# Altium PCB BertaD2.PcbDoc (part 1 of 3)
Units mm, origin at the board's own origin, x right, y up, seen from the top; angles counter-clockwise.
Board outline 100.5 x 100 mm, 4 copper layers (Top Layer, Signal Layer 1, Signal Layer 2, Bottom Layer), stack 0.778 mm thick; 108 components, 216 nets, 850 pads, 807 vias.
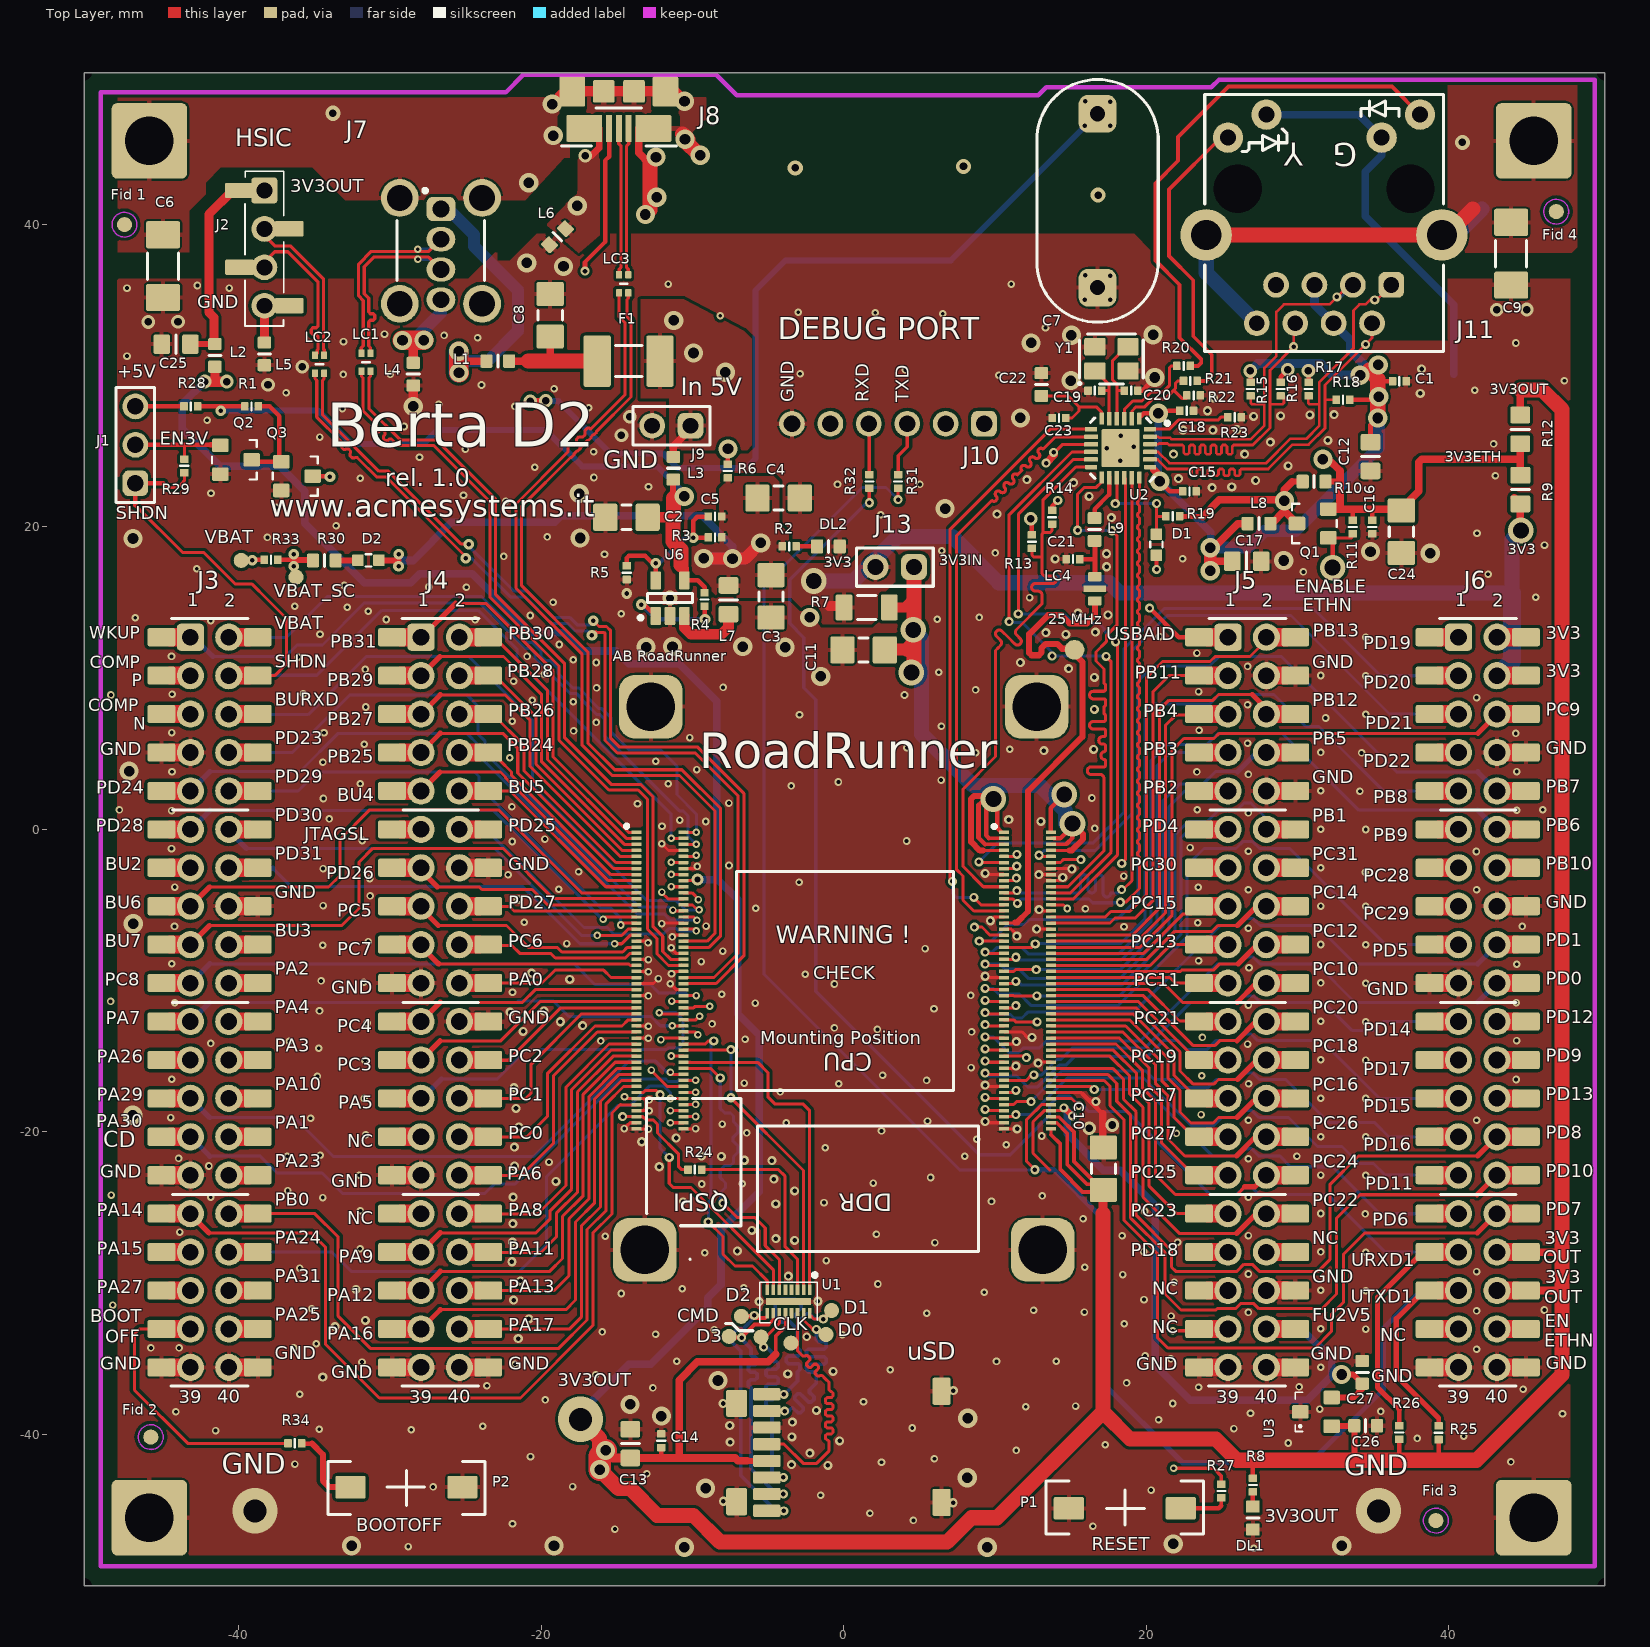
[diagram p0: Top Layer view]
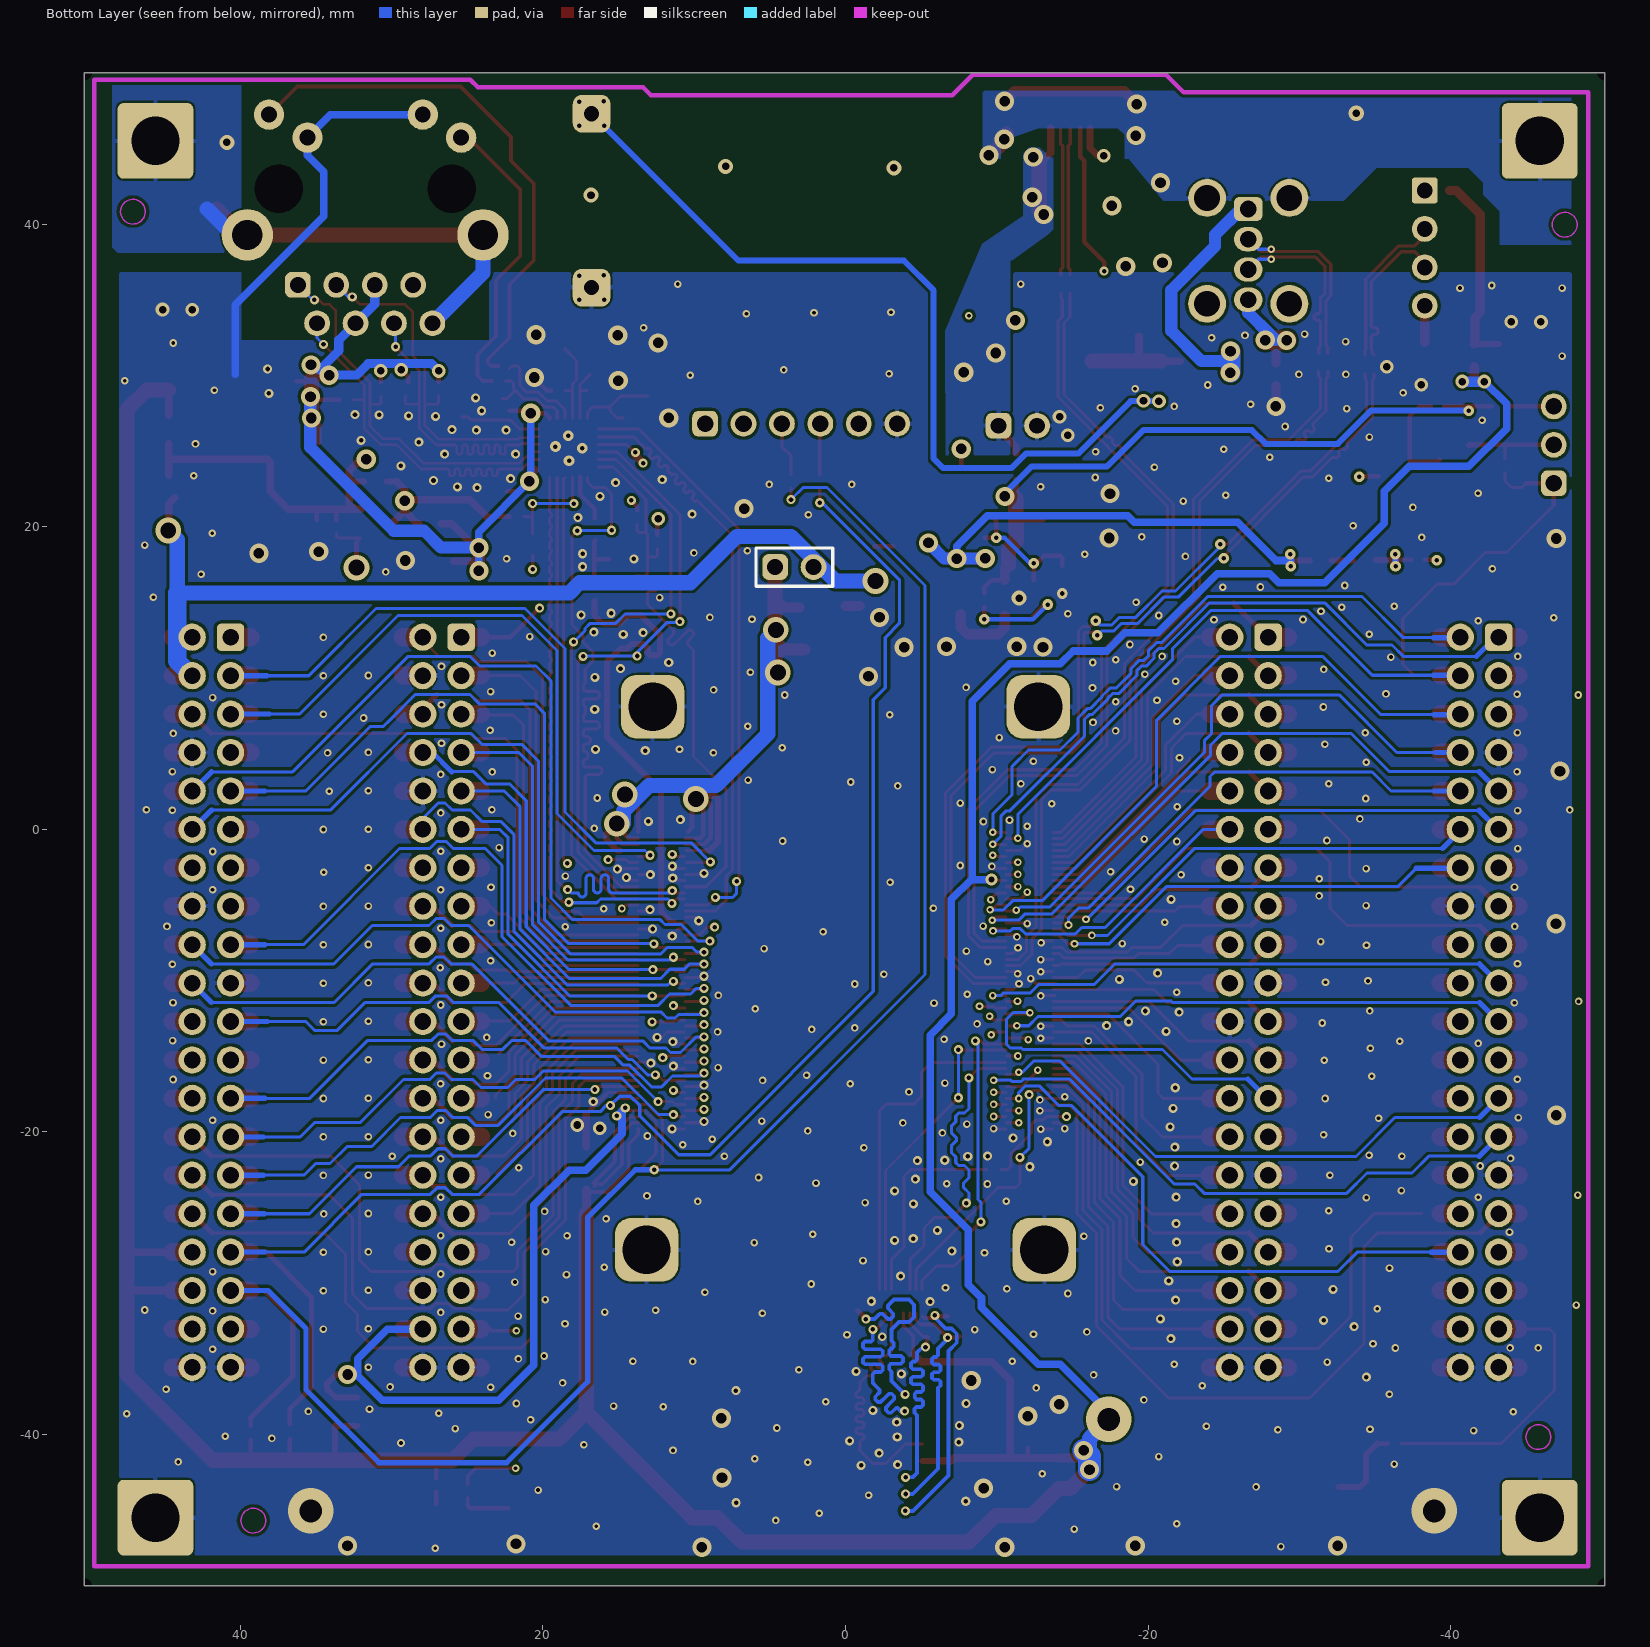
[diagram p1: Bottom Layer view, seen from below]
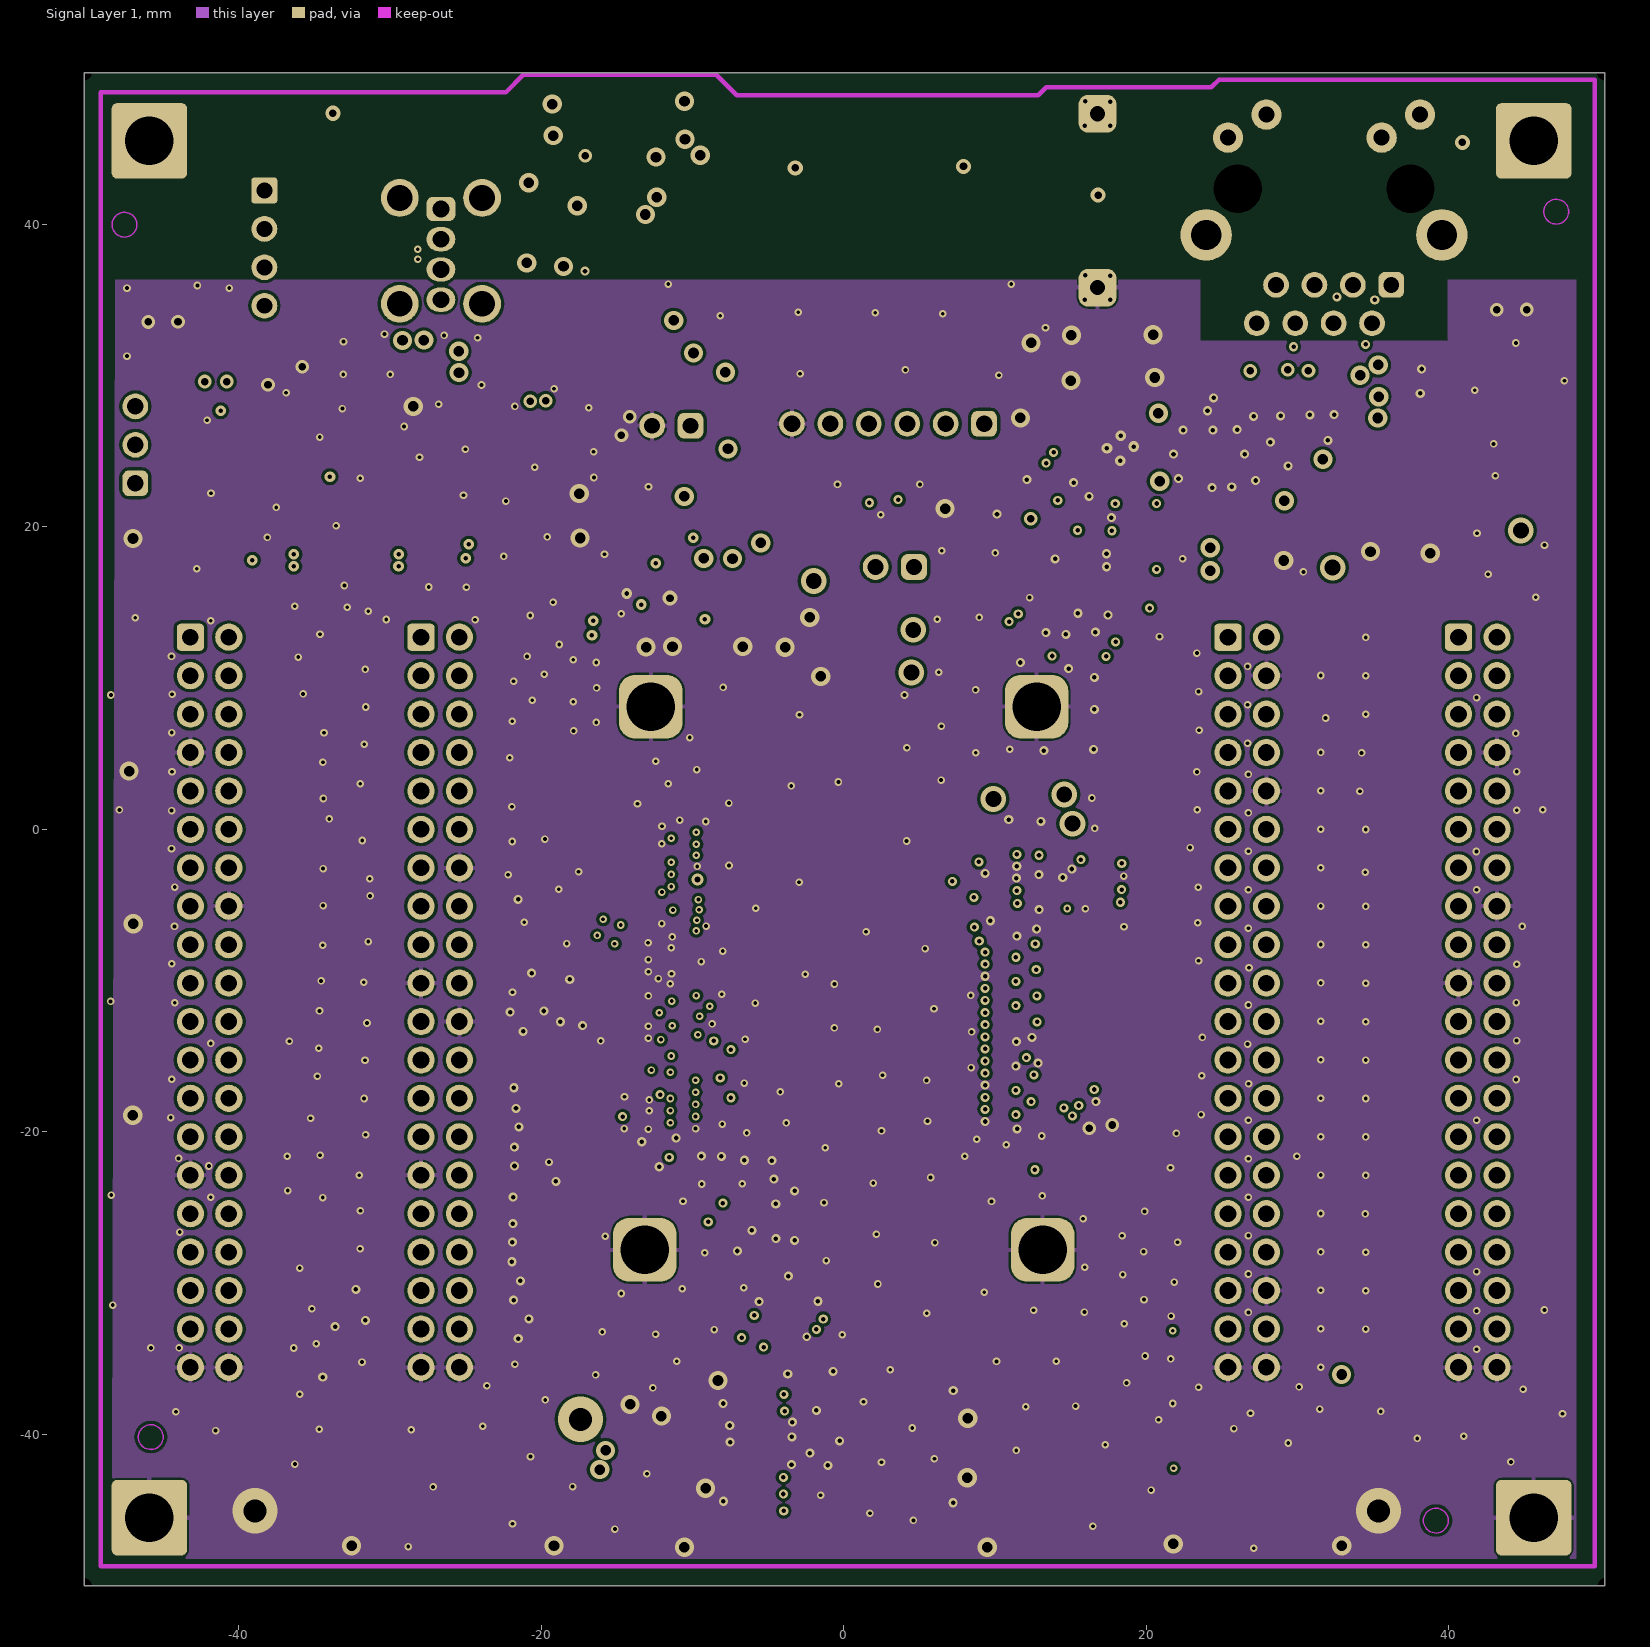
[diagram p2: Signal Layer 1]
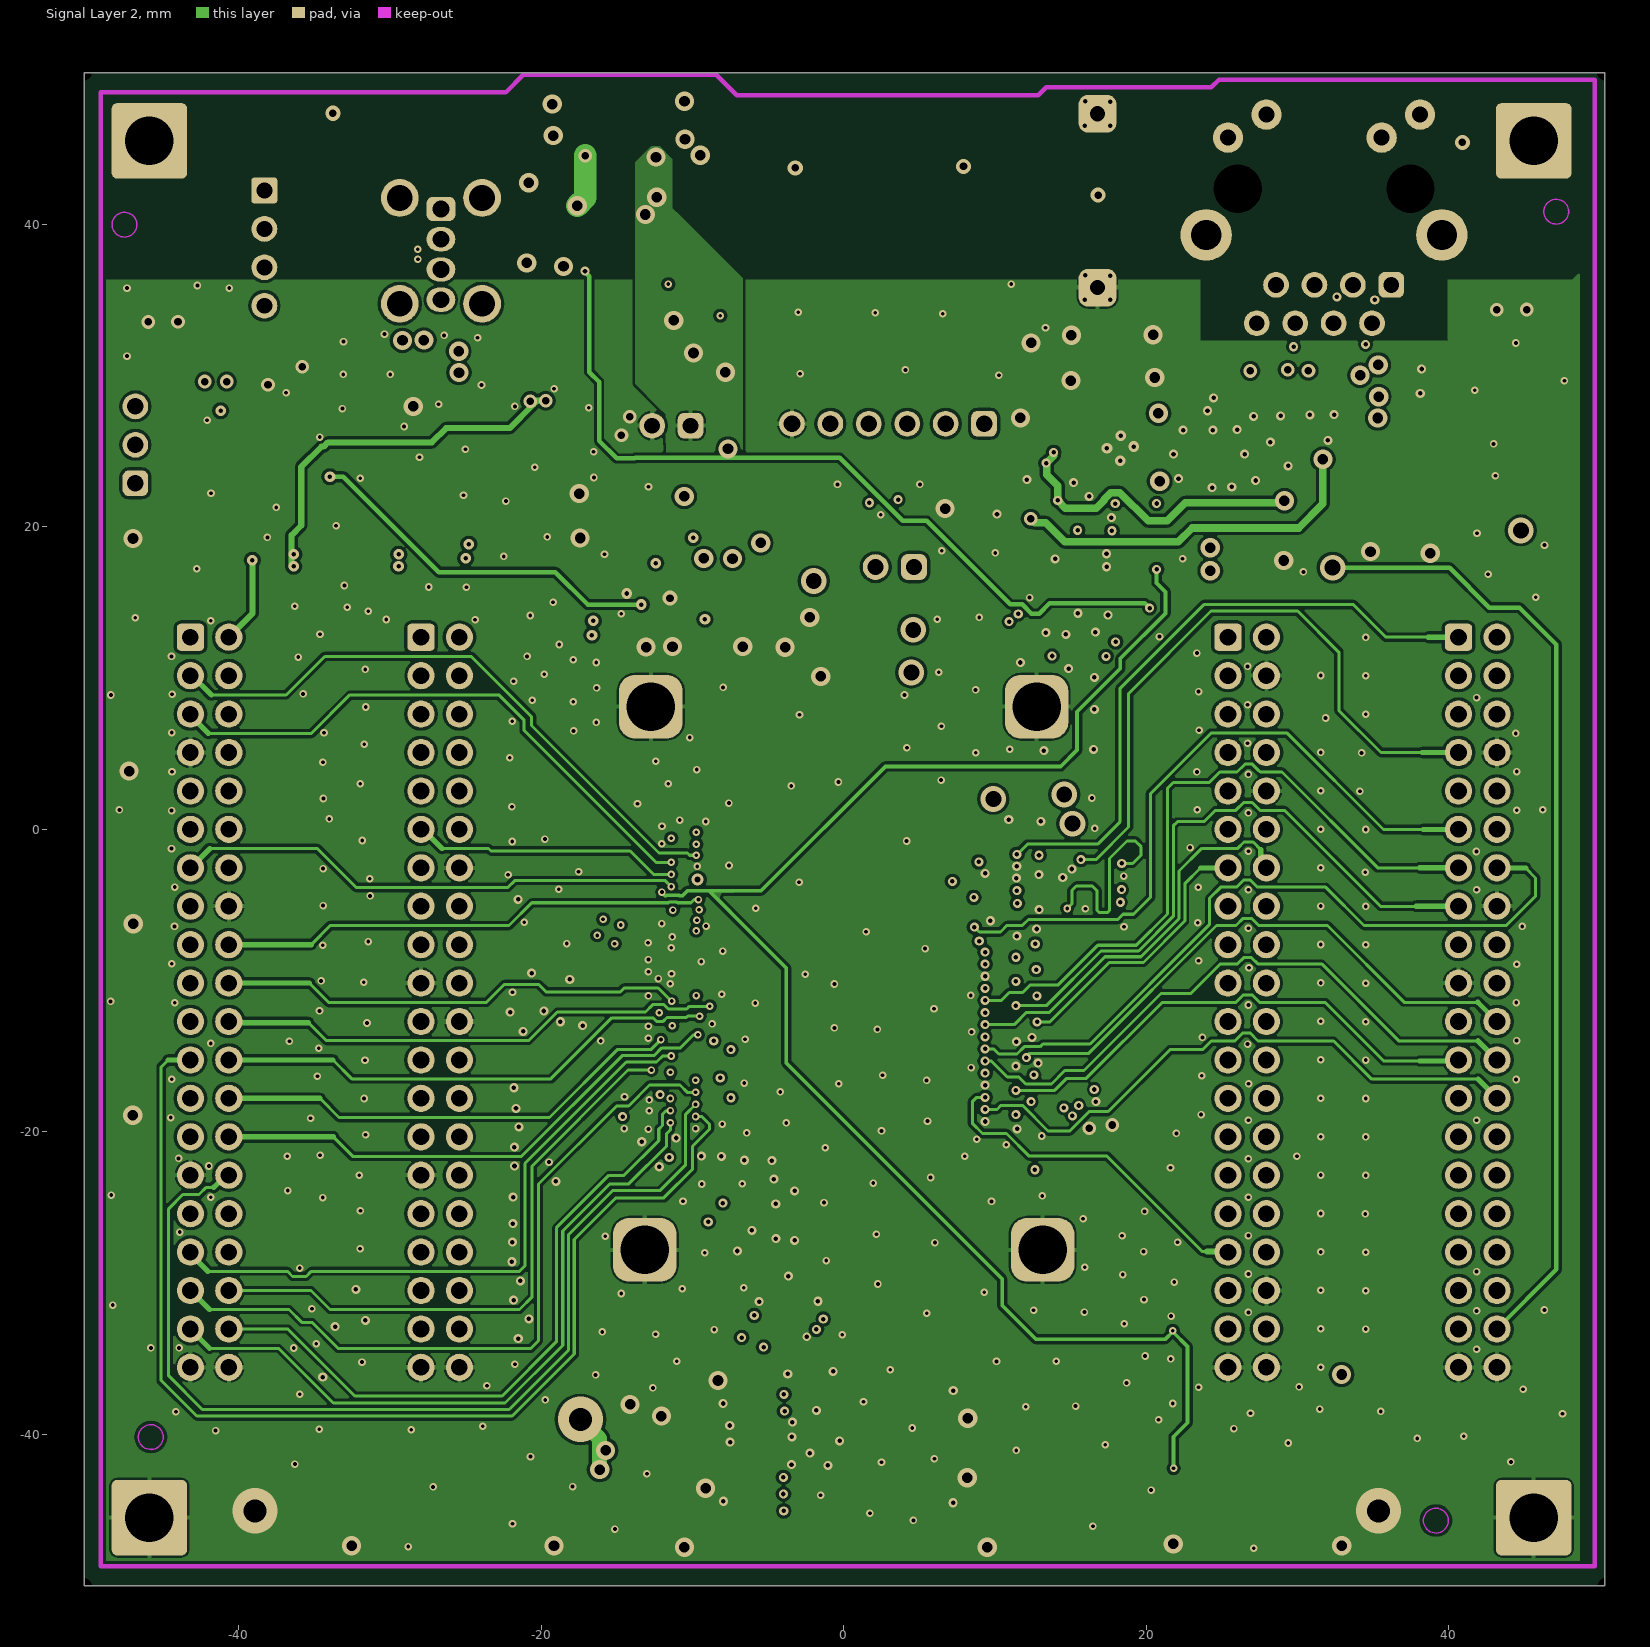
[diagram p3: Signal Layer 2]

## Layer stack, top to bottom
Top Solder: solder mask 0.0102, Solder Resist, Dk 3.5
Top Layer: signal copper 0.0356
Dielectric 1: core 0.254, FR-4, Dk 4.2
Signal Layer 1: signal copper 0.036
Dielectric 3: prepreg 0.127, Dk 4.2
Signal Layer 2: signal copper 0.036
Dielectric 2: core 0.254, Dk 4.2
Bottom Layer: signal copper 0.0356
Bottom Solder: solder mask 0.0102, Solder Resist, Dk 3.5

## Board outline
-50.193,-49.992 -50.193,50.008 -49.193,50.008 -49.193,50.007 50.307,50.007 50.307,-49.992

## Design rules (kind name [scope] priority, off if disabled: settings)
Clearance Clearance_Polygon [InPolygon] p1: gap=0.2
Clearance Clearance_Polygon_EARTH [InPolygon vs InNetClass('EARTH')] p2: gap=0.5
Clearance Clearance_USB [InDifferentialPairClass('USB') vs InDifferentialPairClass('USB')] p3: gap=0.15
Clearance Clearance_track_pad [IsTrack vs IsPad and ExistsOnLayer('Multi-layer')] p4: gap=0.2
Clearance Clearance_J1J2U1U2 [InComponentClass('finepitch')] p5: gap=0.16
Clearance Clearance_rest [All] p6: gap=0.18
ComponentClearance ComponentClearanceFiducials [(InComponent('Fid 1') OR InComponent('Fid 2') OR InComponent('Fid 3') OR InComponent('Fid 4'))] p1: gap=0 collisioncheckmode=3 verticalgap=0 showdistances=FALSE
ComponentClearance ComponentClearance_1 [All] p2: gap=0.254 collisioncheckmode=3 verticalgap=0 showdistances=TRUE
DiffPairsRouting DiffPairsRoutingUSB [InDifferentialPairClass('USB')] p1: maxlimit=0.234 minlimit=0.15 mostfreqgap=0.234 toplayer_maxgap=0.15 toplayer_prefgap=0.15 toplayer_minwidth=0.22 toplayer_maxwidth=0.22 toplayer_prefwidth=0.22 midlayer1_mingap=0.234 midlayer1_minwidth=0.147 midlayer1_maxwidth=0.147 midlayer1_prefwidth=0.147 midlayer2_mingap=0.234 midlayer2_minwidth=0.147 midlayer2_maxwidth=0.147 midlayer2_prefwidth=0.147 bottomlayer_maxgap=0.15 bottomlayer_prefgap=0.15 bottomlayer_minwidth=0.22 bottomlayer_maxwidth=0.22 bottomlayer_prefwidth=0.22 maxuncoupledlength=35
DiffPairsRouting DiffPairsRoutingETH [InDifferentialPairClass('ETH')] p2: maxlimit=0.229 minlimit=0.203 mostfreqgap=0.229 toplayer_maxgap=0.203 toplayer_prefgap=0.203 toplayer_minwidth=0.178 toplayer_maxwidth=0.178 toplayer_prefwidth=0.178 midlayer1_mingap=0.229 midlayer1_minwidth=0.127 midlayer1_maxwidth=0.127 midlayer1_prefwidth=0.127 midlayer2_mingap=0.229 midlayer2_minwidth=0.127 midlayer2_maxwidth=0.127 midlayer2_prefwidth=0.127 bottomlayer_maxgap=0.203 bottomlayer_prefgap=0.203 bottomlayer_minwidth=0.178 bottomlayer_maxwidth=0.178 bottomlayer_prefwidth=0.178 maxuncoupledlength=18
FanoutControl Fanout_Default [All] p5: bgadir=In bgaviamode=Centered fanoutstyle=BGA fanoutdirection=OutThenIn viagrid=0.025 // Fanout_Default (Default Rule)
HoleSize [All] p1: absolutevalues=TRUE maxlimit=3.2 minlimit=0.25 maxpercent=80.000 minpercent=20.000
HoleToHoleClearance [All] p1: gap=0.4 allowstackedmicrovias=TRUE
Length [IsFromTo] p1: maxlimit=37 minlimit=35
MatchedLengths MatchedLengthswithinpair [InDifferentialPairClass('USB') or InDifferentialPairClass('ETH')] p1: tolerance=0.5 checknetsindiffpair=TRUE checkdiffpairvsdiffpair=FALSE checkxsignals=FALSE checkothers=FALSE
MatchedLengths MatchedLengthETH_CPU [InNetClass('ETH_CPU')] p2: tolerance=0.5 checknetsindiffpair=FALSE checkdiffpairvsdiffpair=TRUE checkxsignals=TRUE checkothers=TRUE
MinimumAnnularRing [All] p1: minimumring=0
MinimumSolderMaskSliver [All] p1: minsoldermaskwidth=0.139
NetAntennae [All] p1: netantennaetolerance=3
ParallelSegment [All] p1: limit=254 gap=0.254
PasteMaskExpansion [All] p1: expansion=-0.025
PlaneClearance [All] p1: clearance=0.25
PlaneConnect PlaneConnect_PAD [isPAD] p1: planeconnectstyle=Relief reliefexpansion=0.3 reliefentries=4 reliefconductorwidth=0.4 reliefairgap=0.25
PlaneConnect [All] p2: planeconnectstyle=Direct reliefexpansion=0.508 reliefentries=4 reliefconductorwidth=0.4 reliefairgap=0.254
PolygonConnect "PolygonConnect Pads" [(InPadClass('All Pads'))] p1: connectstyle=Relief reliefconductorwidth=0.3 reliefentries=4 polygonreliefangle="90 Angle" airgapwidth=0.127
PolygonConnect PolygonConnect_NoPads [(Not InPadClass('All Pads'))] p2: connectstyle=Direct reliefconductorwidth=0.254 reliefentries=4 polygonreliefangle="90 Angle" airgapwidth=0.254
RoomDefinition BertaD2 [InComponentClass('BertaD2')] p1: confinementstyle=ConfineIn formatcopy=TRUE lockcomponents=FALSE outline -100.793,-126.192 105.71,-126.192 105.71,93.68 -100.793,93.68
RoomDefinition BertaD2_ETH [InComponentClass('BertaD2_ETH')] p2: confinementstyle=ConfineIn formatcopy=TRUE lockcomponents=FALSE outline -66,-55.879 93.42,-55.879 93.42,74.4 -66,74.4
RoutingCorners [All] p1: cornerstyle=45-Degree minsetback=1 maxsetback=1
RoutingVias RoutingViasDIFF [(InDifferentialPairClass('All Differential Pairs'))] p1: holewidth=0.3 width=0.6 viastyle="Blind Buried (Adjacent Layers)" minholewidth=0.25 minwidth=0.5 maxholewidth=0.5 maxwidth=1
RoutingVias [All] p2: holewidth=0.7 width=0.7 viastyle="Blind Buried (Adjacent Layers)" minholewidth=0.25 minwidth=0.5 maxholewidth=3.2 maxwidth=5
SMDNeckDown SMDNeckDown_Power [(InComponent('r*') OR INCOMPONENT('c*'))] p1: percent=60.000
SMDNeckDown [((InComponent('r*') OR INCOMPONENT('c*'))) AND not( inNet('GND') or inNet('VD*'))] p2: percent=40.000
SilkToSilkClearance [All] p1: silktosilkclearance=0.2
SilkToSolderMaskClearance [IsPad] p1: minsilkscreentomaskgap=0.05 clearancetoexposedcopper=TRUE
SolderMaskExpansion [All] p1: expansion=0.05
Width WidthPower [InNetClass('Power')] p1: maxlimit=3 minlimit=0.127 preferedwidth=0.5 toplayer_minwidth=0.2 midlayer1_minwidth=0.3 midlayer1_maxwidth=0.7 midlayer2_maxwidth=0.7 bottomlayer_minwidth=0.2 minimp=50.000000 maximp=50.000000 favimp=50.000000
Width [All] p2: maxlimit=3 minlimit=0.15 preferedwidth=0.3 midlayer1_prefwidth=0.15 midlayer2_prefwidth=0.15 minimp=50.000000 maximp=50.000000 favimp=50.000000
17 further rules are at their usual default settings.

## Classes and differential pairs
net class EARTH: EARTH1 EARTH2
net class USB: HHSDA_N HHSDA_P HHSDB_N HHSDB_P HHSDC_N HHSDC_P UB_N UB_P UC_N UC_P USBAF_N USBAF_P
differential pair class ETH: RX TX
differential pair class USB: UB UC USBA USBA_DEV USBA_HOST USBAF USBB USBC
component class BertaD2: "AB RoadRunner" C1 C2 C3 C4 C5 C6 C7 C8 C9 C10 C11 C12 C13 C14 C25 C26 C27 D2 DL1 DL2 F1 "Fid 1" "Fid 2" "Fid 3" "Fid 4" J1 J2 J3 J4 J5 J6 J7 J8 J9 J10 J11 J13 J? L1 L2 L3 L4 L5 L6 L7 LC1 LC2 LC3 P1 P2 Q2 Q3 R1 R2 R3 R4 R5 R6 R7 R8 R24 R25 R26 R27 R28 R29 R30 R31 R32 R33 R34 U1 U3 U6 uSD
component class BertaD2_ETH: "25 MHz" C15 C16 C17 C18 C19 C20 C21 C22 C23 C24 D1 GN1 L8 L9 LC4 Q1 R9 R10 R11 R12 R13 R14 R15 R16 R17 R18 R19 R20 R21 R22 R23 U2 Y1
net class ETH: RX_N RX_P TX_N TX_P
net class microSDheader: SD_CLK SD_CMD SD_DATA0 SD_DATA1 SD_DATA2 SD_DATA3
net class microSDmicro: PA18 PA19 PA20 PA21 PA22 PA28 SDCLK
net class POWER: 3V3_IO_ETH 3V3_IO_ETH_F
component class finepitch: "AB RoadRunner" U1 U2
net class ETH_CPU: ETH_CRS ETH_MDC ETH_MDIO ETH_RX0 ETH_RX1 ETH_RXER ETH_TX0 ETH_TX1 ETH_TXEN
differential pair HHSDC: +HHSDC_P -HHSDC_N
differential pair HHSDB: +HHSDB_P -HHSDB_N
differential pair HHSDA: +HHSDA_P -HHSDA_N
differential pair USBAF: +USBAF_P -USBAF_N
differential pair UC: +UC_P -UC_N
differential pair UB: +UB_P -UB_N
differential pair RX: +RX_P -RX_N
differential pair TX: +TX_P -TX_N

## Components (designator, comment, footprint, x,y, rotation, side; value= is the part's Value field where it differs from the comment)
"25 MHz" "GN TEST POINT" "TP 1.3mm" 15.26,11.87 r90 top
"AB RoadRunner" "ACME Board RoadRunner" "AB ROADRUNNER" 0,-9.992 r90 top locked
C1 "CC 100nF 10V" "CC 0402S 1005m SOLDER" 36.73,29.62 r180 top
C2 "CC 100uF 6.3V" "CC 1206 (3216 metric)" -14.358,20.628 r180 top
C3 "CC 100uF 6.3V" "CC 1206 (3216 metric)" -4.8,15.4 r270 top
C4 "CC 100uF 6.3V" "CC 1206 (3216 metric)" -4.3,21.9 r0 top
C5 "18pF" "CC 0402S 1005m SOLDER" -8.5,20.68 r180 top
C6 "CC 1nF 3kV" "CC 1808 (4520 metric)" -44.99,37.23 r90 top
C7 "CE Supercap 0F47 - 5V" "Supercap AVX 8x16x18" 16.78,41.555 r270 top
C8 "CC 100uF 6.3V" "CC 1206 (3216 metric)" -19.4,33.98 r90 top
C9 "CC 1nF 3kV" "CC 1808 (4520 metric)" 44.12,38.05 r90 top
C10 "CC 47uF 6.3V" "CC 1206 (3216 metric)" 17.17,-22.43 r90 top
C11 "CC 47uF 6.3V" "CC 1206 (3216 metric)" 1.32,11.86 r180 top
C12 "CC 10uF" "CC 0805 (2012 metric)" 34.82,24.64 r90 top
C13 "10uF" "CC 0805 (2012 metric)" -14.1,-40.6 r270 top
C14 "100nF" "CC 0402S 1005m SOLDER" -12.06,-40.41 r270 top
C15 "100nF" "CC 0402S 1005m SOLDER" 22.85,22.34 r0 top
C16 "100nF" "CC 0402S 1005m SOLDER" 34.94,19.98 r270 top
C17 "1uF" "CC 0805 (2012 metric)" 26.64,17.72 r180 top
C18 "100nF" "CC 0402S 1005m SOLDER" 22.67,27.67 r180 top
C19 "33pF" "CC 0402S 1005m SOLDER" 16.6,29 r0 top
C20 "27pF" "CC 0402S 1005m SOLDER" 19,29 r180 top
C21 "18pF N.M." "CC 0402S 1005m SOLDER" 15.15,17.86 r0 top
C22 "1uF" "CC 0603 (1608 metric)" 13.069,29.407 r270 top
C23 "470pF" "CC 0402S 1005m SOLDER" 14.23,27.19 r0 top
C24 "10uF" "CC 1206 (3216 metric)" 36.86,19.67 r270 top
C25 "CC 10uF 10V" "CC 0805 (2012 metric)" -44.13,32.07 r0 top
C26 "1uF" "CC 0603 (1608 metric)" 34.5,-39.42 r0 top
C27 "1uF" "CC 0603 (1608 metric)" 34.28,-35.89 r270 top
D1 "DS 100mA 0603 30V" "DD 0603" 20.67,18.82 r90 top
D2 "DS 100mA 0603 30V" "DD 0603" -31.414,17.785 r0 top
DL1 "GREEN" "DL 0603 (1608 metric) GREEN" 27.05,-45.52 r90 top
DL2 "GREEN" "DL 0603 (1608 metric) GREEN" -1.01,18.7 r180 top
F1 "FU BOURNS" "FU 1812 (4532 metric)" -14.22,30.95 r180 top
"Fid 1" "FF ACME" "Fiducial 1mm_small" -47.54,39.97 r90 top
"Fid 2" "FF ACME" "Fiducial 1mm_small" -45.8,-40.17 r90 top
"Fid 3" "FF ACME" "Fiducial 1mm_small" 39.14,-45.69 r90 top
"Fid 4" "FF ACME" "Fiducial 1mm_small" 47.1,40.83 r90 top
J1 "JJ HDR 1x3 2.54mm N.M." "HDR 1x3" -46.818,22.877 r90 top
J2 "JJ HDR 1x4 2.54mm" "HDR1X4 - Female DualMount" -38.29,42.23 r270 top
J3 "JJ HDR2X20RM SMD F" "HDR2X20 SMD Female"#1 -41.91,-11.43 r270 top locked
J4 "JJ HDR2X20RM SMD F" "HDR2X20 SMD Female"#1 -26.67,-11.43 r270 top locked
J5 "JJ HDR2X20RM SMD F" "HDR2X20 SMD Female"#2 26.67,-11.43 r270 top locked
J6 "JJ HDR2X20RM SMD F" "HDR2X20 SMD Female"#3 41.91,-11.43 r270 top
J7 "JJ USB A" "USB2.0-4H4 3D FOX" -26.622,35.01 r270 top
J8 "JJ USB Micro SMD" "USB Micro B - Extended" -14.86,49.28 r180 top
J9 "JJ HDR1X2" "HDR1X2 NAKED" -11.39,26.68 r180 top
J10 "JJ HDR1X6 6mm M" "HDR1X6 3D" 9.28,26.81 r180 top
J11 "JJ RJLD260TC1 ETH" RJLD-260TC1 31.75,39.29 r180 top
J13 "JJ HDR1X2" "HDR1X2 NAKED" 3.38,17.34 r180 top
L1 "LF 221" "LL 0603 (1608 metric)" -22.86,30.95 r0 top
L2 "LF 221" "LL 0603 (1608 metric)" -41.56,31.33 r270 top
L3 "LF 221" "LL 0603 (1608 metric)" -11.26,23.87 r270 top
L4 "LF 221" "LL 0603 (1608 metric)" -28.45,30.09 r270 top
L5 "LF 221" "LL 0603 (1608 metric)" -38.29,31.43 r270 top
L6 "LF 221" "LL 0603 (1608 metric)" -18.92,39.17 r225 top
L7 "2uH2" "LL 0805 (2012 metric)" -7.614,15.173 r270 top
L8 "220@100Mhz" "LL 0603 (1608 metric)" 27.45,20.21 r0 top
L9 "120@100Mhz" "LL 0603 (1608 metric)" 16.58,19.82 r270 top
LC1 "LC 90 150mA 0504" "LC 0504 (1210 metric)" -31.58,30.88 r90 top
LC2 "LC 90 150mA 0504" "LC 0504 (1210 metric)" -34.64,30.74 r90 top
LC3 "LC 90 150mA 0504" "LC 0504 (1210 metric)" -14.54,36.06 r90 top
LC4 "LC filter 0603" "LC 0603 (1608 metric)" 16.6,15.9 r90 top
P1 "SW KTH33050" "PULSANTE SMD S" 18.58,-44.89 r90 top
P2 "SW KTH33050" "PULSANTE SMD S" -28.9,-43.47 r270 top
Q1 "MP 3A SOT23 20V" "SOT23 for IRLML6402" 30.98,20.22 r90 top
Q2 "MN 100mA SOT23 50V" "SOT23 for IRLML6402" -40.15,24.43 r270 top
Q3 "MN 100mA SOT23 50V" "SOT23 for IRLML6402" -36.12,23.35 r270 top
R1 "RR 100k" "CC 0402S 1005m SOLDER" -39.141,27.955 r180 top
R2 "1k" "CC 0402S 1005m SOLDER" -3.6,18.7 r180 top
R3 "1M 1%" "CC 0402S 1005m SOLDER" -8.5,19.3 r180 top
R4 "RR 100k" "CC 0402S 1005m SOLDER" -9.2,15.2 r90 top
R5 "220k 1%" "CC 0402S 1005m SOLDER" -14.338,16.968 r90 top
R6 "RR 47k 5%" "RR 0402S 1005m SOLDER" -7.66,23.68 r270 top
R7 "RR 0R1 0805 5%" "RR 1206 (3216 metric)" 1.52,14.67 r180 top
R8 "1k" "CC 0402S 1005m SOLDER" 27.05,-43.34 r90 top
R9 "RR 0R 0805 5% N.M." "RR 0805 (2012 metric)" 44.73,22.46 r270 top
R10 "N.M." "RR 0603 (1608 metric)" 31.09,22.99 r0 top
R11 "10k" "RR 0402S 1005m SOLDER" 33.65,19.99 r90 top
R12 "RR 0R 0805 5%" "RR 0805 (2012 metric)" 44.72,26.44 r90 top
R13 "1k5" "RR 0402S 1005m SOLDER" 12.44,19.02 r90 top
R14 "N.M." "RR 0402S 1005m SOLDER" 13.77,20.63 r90 top
R15 "49R9" "RR 0402S 1005m SOLDER" 26.9,29.1 r270 top
R16 "49R9" "RR 0402S 1005m SOLDER" 28.89,29.1 r270 top
R17 "49R9" "RR 0402S 1005m SOLDER" 30.73,29.1 r270 top
R18 "49R9" "RR 0402S 1005m SOLDER" 33,28.4 r180 top
R19 "RR 1k 5%" "RR 0402S 1005m SOLDER" 21.75,20.7 r0 top
R20 "RR 1k 5%" "RR 0402S 1005m SOLDER" 22.47,30.63 r180 top
R21 "RR 1k 5%" "RR 0402S 1005m SOLDER" 22.91,29.64 r180 top
R22 "RR 10k 5%" "RR 0402S 1005m SOLDER" 23.13,28.68 r0 top
R23 "12k1 1%" "RR 0402S 1005m SOLDER" 25.84,27.24 r180 top
R24 "RR 39R" "RR 0402S 1005m SOLDER" -9.84,-22.49 r180 top
R25 "RR 68k 5%" "RR 0402S 1005m SOLDER" 39.32,-39.88 r90 top
R26 "RR 68k 5%" "RR 0402S 1005m SOLDER" 36.72,-39.86 r90 top
R27 "RR 100k" "CC 0402S 1005m SOLDER" 24.961,-43.733 r270 top
R28 "RR 100k" "CC 0402S 1005m SOLDER" -43.154,27.953 r0 top
R29 "RR 0R" "CC 0402S 1005m SOLDER" -43.584,24.028 r270 top
R30 "RR 100R" "RR 0603 (1608 metric)" -34.33,17.77 r0 top
R31 "RR 4k7 5%" "RR 0402S 1005m SOLDER" 3.6,23 r90 top
R32 "RR 4k7 5%" "RR 0402S 1005m SOLDER" 1.7,23 r90 top
R33 "RR 1k" "CC 0402S 1005m SOLDER" -37.85,17.82 r0 top
R34 "RR 1k" "CC 0402S 1005m SOLDER" -36.28,-40.58 r0 top
U1 "CM1624" CM1624 -3.65,-31.2 r180 top
U2 "LAN8720A" "QFN24 - 4x4mm" 18.3,25.2 r270 top
U3 "AP7333-25SAG" "SOT23 generic" 31.2,-38.5 r90 top
U6 "IC NCP1529" "IC SOT23-5" -11.48,15.287 r90 top
uSD "microSD hinge socket" "microSDHinge JAE E" 1.145,-41.19 r270 top
Y1 "25 MHz" "XT DFN-LCC 3.2x2.5" 17.7,31.1 r0 top

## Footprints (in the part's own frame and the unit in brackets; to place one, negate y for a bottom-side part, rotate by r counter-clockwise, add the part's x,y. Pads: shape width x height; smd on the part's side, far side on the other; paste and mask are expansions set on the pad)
"AB ROADRUNNER" [mm]
  rrect20% 0.23x0.66 smd paste-0.01 mask+0.015: J1-1(9.8,13.705) J1-2(9.8,10.595) J1-3(9.4,13.705) J1-4(9.4,10.595) J1-5(9,13.705) J1-6(9,10.595) J1-7(8.6,13.705) J1-8(8.6,10.595) J1-9(8.2,13.705) J1-10(8.2,10.595) J1-11(7.8,13.705) J1-12(7.8,10.595) J1-13(7.4,13.705) J1-14(7.4,10.595) J1-15(7,13.705) J1-16(7,10.595) J1-17(6.6,13.705) J1-18(6.6,10.595) J1-19(6.2,13.705) J1-20(6.2,10.595) J1-21(5.8,13.705) J1-22(5.8,10.595) J1-23(5.4,13.705) J1-24(5.4,10.595) J1-25(5,13.705) J1-26(5,10.595) J1-27(4.6,13.705) J1-28(4.6,10.595) J1-29(4.2,13.705) J1-30(4.2,10.595) J1-31(3.8,13.705) J1-32(3.8,10.595) J1-33(3.4,13.705) J1-34(3.4,10.595) J1-35(3,13.705) J1-36(3,10.595) J1-37(2.6,13.705) J1-38(2.6,10.595) J1-39(2.2,13.705) J1-40(2.2,10.595) J1-41(1.8,13.705) J1-42(1.8,10.595) J1-43(1.4,13.705) J1-44(1.4,10.595) J1-45(1,13.705) J1-46(1,10.595) J1-47(0.6,13.705) J1-48(0.6,10.595) J1-49(0.2,13.705) J1-50(0.2,10.595) J1-51(-0.2,13.705) J1-52(-0.2,10.595) J1-53(-0.6,13.705) J1-54(-0.6,10.595) J1-55(-1,13.705) J1-56(-1,10.595) J1-57(-1.4,13.705) J1-58(-1.4,10.595) J1-59(-1.8,13.705) J1-60(-1.8,10.595) J1-61(-2.2,13.705) J1-62(-2.2,10.595) J1-63(-2.6,13.705) J1-64(-2.6,10.595) J1-65(-3,13.705) J1-66(-3,10.595) J1-67(-3.4,13.705) J1-68(-3.4,10.595) J1-69(-3.8,13.705) J1-70(-3.8,10.595) J1-71(-4.2,13.705) J1-72(-4.2,10.595) J1-73(-4.6,13.705) J1-74(-4.6,10.595) J1-75(-5,13.705) J1-76(-5,10.595) J1-77(-5.4,13.705) J1-78(-5.4,10.595) J1-79(-5.8,13.705) J1-80(-5.8,10.595) J1-81(-6.2,13.705) J1-82(-6.2,10.595) J1-83(-6.6,13.705) J1-84(-6.6,10.595) J1-85(-7,13.705) J1-86(-7,10.595) J1-87(-7.4,13.705) J1-88(-7.4,10.595) J1-89(-7.8,13.705) J1-90(-7.8,10.595) J1-91(-8.2,13.705) J1-92(-8.2,10.595) J1-93(-8.6,13.705) J1-94(-8.6,10.595) J1-95(-9,13.705) J1-96(-9,10.595) J1-97(-9.4,13.705) J1-98(-9.4,10.595) J1-99(-9.8,13.705) J1-100(-9.8,10.595) J2-1(9.8,-10.595) J2-2(9.8,-13.705) J2-3(9.4,-10.595) J2-4(9.4,-13.705) J2-5(9,-10.595) J2-6(9,-13.705) J2-7(8.6,-10.595) J2-8(8.6,-13.705) J2-9(8.2,-10.595) J2-10(8.2,-13.705) J2-11(7.8,-10.595) J2-12(7.8,-13.705) J2-13(7.4,-10.595) J2-14(7.4,-13.705) J2-15(7,-10.595) J2-16(7,-13.705) J2-17(6.6,-10.595) J2-18(6.6,-13.705) J2-19(6.2,-10.595) J2-20(6.2,-13.705) J2-21(5.8,-10.595) J2-22(5.8,-13.705) J2-23(5.4,-10.595) J2-24(5.4,-13.705) J2-25(5,-10.595) J2-26(5,-13.705) J2-27(4.6,-10.595) J2-28(4.6,-13.705) J2-29(4.2,-10.595) J2-30(4.2,-13.705) J2-31(3.8,-10.595) J2-32(3.8,-13.705) J2-33(3.4,-10.595) J2-34(3.4,-13.705) J2-35(3,-10.595) J2-36(3,-13.705) J2-37(2.6,-10.595) J2-38(2.6,-13.705) J2-39(2.2,-10.595) J2-40(2.2,-13.705) J2-41(1.8,-10.595) J2-42(1.8,-13.705) J2-43(1.4,-10.595) J2-44(1.4,-13.705) J2-45(1,-10.595) J2-46(1,-13.705) J2-47(0.6,-10.595) J2-48(0.6,-13.705) J2-49(0.2,-10.595) J2-50(0.2,-13.705) J2-51(-0.2,-10.595) J2-52(-0.2,-13.705) J2-53(-0.6,-10.595) J2-54(-0.6,-13.705) J2-55(-1,-10.595) J2-56(-1,-13.705) J2-57(-1.4,-10.595) J2-58(-1.4,-13.705) J2-59(-1.8,-10.595) J2-60(-1.8,-13.705) J2-61(-2.2,-10.595) J2-62(-2.2,-13.705) J2-63(-2.6,-10.595) J2-64(-2.6,-13.705) J2-65(-3,-10.595) J2-66(-3,-13.705) J2-67(-3.4,-10.595) J2-68(-3.4,-13.705) J2-69(-3.8,-10.595) J2-70(-3.8,-13.705) J2-71(-4.2,-10.595) J2-72(-4.2,-13.705) J2-73(-4.6,-10.595) J2-74(-4.6,-13.705) J2-75(-5,-10.595) J2-76(-5,-13.705) J2-77(-5.4,-10.595) J2-78(-5.4,-13.705) J2-79(-5.8,-10.595) J2-80(-5.8,-13.705) J2-81(-6.2,-10.595) J2-82(-6.2,-13.705) J2-83(-6.6,-10.595) J2-84(-6.6,-13.705) J2-85(-7,-10.595) J2-86(-7,-13.705) J2-87(-7.4,-10.595) J2-88(-7.4,-13.705) J2-89(-7.8,-10.595) J2-90(-7.8,-13.705) J2-91(-8.2,-10.595) J2-92(-8.2,-13.705) J2-93(-8.6,-10.595) J2-94(-8.6,-13.705) J2-95(-9,-10.595) J2-96(-9,-13.705) J2-97(-9.4,-10.595) J2-98(-9.4,-13.705) J2-99(-9.8,-10.595) J2-100(-9.8,-13.705)
  rrect50% 4.2x4.2 hole 3.2 paste-3 mask+0.03: J1-101(18.1,12.75) J1-102(-17.8,13.15) J2-101(18.1,-12.75) J2-102(-17.8,-13.15)
  silkscreen extent 10.07,-10.06 10.31,14.46, body extent -19.65,-15 20.35,15, height 4.41
"CC 0402S 1005m SOLDER" [mm] "Generic chip capacitor with small footprint"
  rrect15% 0.5x0.56 smd paste-0.01 mask+0.04: 1(0.45,0) 2(-0.45,0)
  silkscreen extent 0,-0.26 0,0.26, body extent -0.5,-0.25 0.5,0.25, height 0.5
"CC 0603 (1608 metric)" [mm] "Generic chip capacitor"
  rrect25% 0.8x0.9 smd paste-0.05: 1(0.75,0) 2(-0.75,0)
  silkscreen extent 0,-0.4 0,0.4, body extent -0.8,-0.4 0.8,0.4, height 0.8
"CC 0805 (2012 metric)" [mm] "Generic chip capacitor"
  rrect25% 1.1x1.3 smd paste-0.05: 1(0.95,0) 2(-0.95,0)
  silkscreen extent 0,-0.6 0,0.6, body extent -1,-0.63 1,0.63, height 1.25
"CC 1206 (3216 metric)" [mm] "Generic chip capacitor"
  rrect15% 1.6x1.8 smd paste-0.05: 1(-1.4,0) 2(1.4,0)
  silkscreen extent -0.3,-0.8 0.3,0.8, body extent -1.6,-0.8 1.6,0.8, height 1.6
"CC 1808 (4520 metric)" [mm] "Generic chip capacitor"
  rrect15% 1.8x2.25 smd: 1(-2.075,0) 2(2.075,0)
  silkscreen extent -0.87,-1.02 0.87,1.02, body extent -2.25,-1 2.25,1, height 2.03
CM1624 [mm] "EMI Filter for T-Flash /  MicroSD Interfaces"
  rrect20% 0.24x0.7 smd paste-0.022 mask+0.01: 1(-1.4,-0.77) 2(-1,-0.77) 3(-0.6,-0.77) 4(-0.2,-0.77) 5(0.2,-0.77) 6(0.6,-0.77) 7(1,-0.77) 8(1.4,-0.77) 9(1.4,0.77) 10(1,0.77) 11(0.6,0.77) 12(0.2,0.77) 13(-0.2,0.77) 14(-0.6,0.77) 15(-1,0.77) 16(-1.4,0.77)
  rrect20% 3x0.45 smd paste-2 mask+0.01: 17(0,0)
  silkscreen extent -1.9,-2.79 6.51,1.4, body extent -1.65,-0.68 1.65,0.68, height 1.11
"DD 0603" [mil] "SMD General purpose rectifiers"
  rrect15% 30x30 smd: A(27.44,0) K(-27.56,0)
  silkscreen extent -8,-16 7,16, body extent -31,-16 31,16, height 18
"DL 0603 (1608 metric) GREEN" [mm] "Led 1608-0603"
  rrect10% 0.8x0.9 smd: A(0.75,0)
  rrect15% 0.8x0.9 smd: K(-0.75,0)
  silkscreen extent 0,-0.4 0,0.4, body extent -0.8,-0.4 0.8,0.4, height 0.58
"Fiducial 1mm_small" [mm] "Fiducial da 1MM"
  round 1 smd paste-1 mask+0.4: FID(0,0)
  Keep-Out Layer circle w0.1: c0,0 r0.82
"FU 1812 (4532 metric)" [mm] "Generic chip capacitor"
  rrect15% 1.8x3.4 smd: 1(-2.075,0) 2(2.075,0)
  silkscreen extent -0.87,-1.02 0.87,1.02, body extent -2.25,-1.6 2.25,1.6, height 1.04
"HDR1X2 NAKED" [mm] "Connector; Header; 2 Position"
  rrect50% 1.7x1.7 hole 1.05: 1(-1.27,0)
  round 1.7 hole 1.05: 2(1.27,0)
  silkscreen extent -2.54,-1.27 2.54,1.27
"HDR1X4 - Female DualMount" [mm] "Connector; Header Female; 6 Position DualMount"
  rrect20% 1.7x1.7 hole 1.05: 1(0,0)
  rrect20% 1.02x1.91 smd: 1(0,-1.645) 2(2.53,1.645) 3(5.08,-1.645) 4(7.61,1.645)
  round 1.7 hole 1.05: 2(2.54,0) 3(5.08,0) 4(7.62,0)
  silkscreen extent -1.27,-1.28 8.97,1.28, body extent -1.23,-1.27 8.93,1.27, height 8.65
"HDR1X6 3D" [mm] "Connector; Header; 6 Position"
  rrect50% 1.7x1.7 hole 1.1: 1(0,0)
  round 1.7 hole 1.1: 2(2.54,0) 3(5.08,0) 4(7.62,0) 5(10.16,0) 6(12.7,0)
  body extent -1.08,-1.16 13.76,1.18, height 8.23
"HDR2X20 SMD Female"#1 [mm] "Connector SMD Female reverse mount 20x2 Position"
  rrect20% 1.2x1.83 smd paste-5: 1(-24.13,-3.185) 2(-24.13,3.185) 3(-21.59,-3.185) 4(-21.59,3.185) 5(-19.05,-3.185) 6(-19.05,3.185) 7(-16.51,-3.185) 8(-16.51,3.185) 9(-13.97,-3.185) 10(-13.97,3.185) 11(-11.43,-3.185) 12(-11.43,3.185) 13(-8.89,-3.185) 14(-8.89,3.185) 15(-6.35,-3.185) 16(-6.35,3.185) 17(-3.81,-3.185) 18(-3.81,3.185) 19(-1.27,-3.185) 20(-1.27,3.185) 21(1.27,-3.185) 22(1.27,3.185) 23(3.81,-3.185) 24(3.81,3.185) 25(6.35,-3.185) 26(6.35,3.185) 27(8.89,-3.185) 28(8.89,3.185) 29(11.43,-3.185) 30(11.43,3.185) 31(13.97,-3.185) 32(13.97,3.185) 33(16.51,-3.185) 34(16.51,3.185) 35(19.05,-3.185) 36(19.05,3.185) 37(21.59,-3.185) 38(21.59,3.185) 39(24.13,-3.185) 40(24.13,3.185)
  rrect30% 1.8x1.8 hole 1.1: 1(-24.13,-1.27)
  round 1.8 hole 1.1: 2(-24.13,1.27) 3(-21.59,-1.27) 4(-21.59,1.27) 5(-19.05,-1.27) 6(-19.05,1.27) 7(-16.51,-1.27) 8(-16.51,1.27) 9(-13.97,-1.27) 10(-13.97,1.27) 11(-11.43,-1.27) 12(-11.43,1.27) 13(-8.89,-1.27) 14(-8.89,1.27) 15(-6.35,-1.27) 16(-6.35,1.27) 17(-3.81,-1.27) 18(-3.81,1.27) 19(-1.27,-1.27) 20(-1.27,1.27) 21(1.27,-1.27) 22(1.27,1.27) 23(3.81,-1.27) 24(3.81,1.27) 25(6.35,-1.27) 26(6.35,1.27) 27(8.89,-1.27) 28(8.89,1.27) 29(11.43,-1.27) 30(11.43,1.27) 31(13.97,-1.27) 32(13.97,1.27) 33(16.51,-1.27) 34(16.51,1.27) 35(19.05,-1.27) 36(19.05,1.27) 37(21.59,-1.27) 38(21.59,1.27) 39(24.13,-1.27) 40(24.13,1.27)
  Top Layer lines w1.2: 24.13,-2.57 24.13,-1.27 ; 21.59,-2.57 21.59,-1.27 ; 19.05,-2.57 19.05,-1.27 ; 16.51,-2.57 16.51,-1.27 ; 13.97,-2.57 13.97,-1.27 ; 11.43,-2.57 11.43,-1.27 ; 8.89,-2.57 8.89,-1.27 ; 6.35,-2.57 6.35,-1.27 ; 3.81,-2.57 3.81,-1.27 ; 1.27,-2.57 1.27,-1.27 ; -1.27,-2.57 -1.27,-1.27 ; -3.81,-2.57 -3.81,-1.27 ; -6.35,-2.57 -6.35,-1.27 ; -8.89,-2.57 -8.89,-1.27 ; -11.43,-2.57 -11.43,-1.27 ; -13.97,-2.57 -13.97,-1.27 ; -16.51,-2.57 -16.51,-1.27 ; -19.05,-2.57 -19.05,-1.27 ; -21.59,-2.57 -21.59,-1.27 ; -24.13,-2.57 -24.13,-1.27 ; 24.13,1.27 24.13,2.57 ; 21.59,1.27 21.59,2.57 ; 19.05,1.27 19.05,2.57 ; 16.51,1.27 16.51,2.57 ; 13.97,1.27 13.97,2.57 ; 11.43,1.27 11.43,2.57 ; 8.89,1.27 8.89,2.57 ; 6.35,1.27 6.35,2.57 ; 3.81,1.27 3.81,2.57 ; 1.27,1.27 1.27,2.57 ; -1.27,1.27 -1.27,2.57 ; -3.81,1.27 -3.81,2.57 ; -6.35,1.27 -6.35,2.57 ; -8.89,1.27 -8.89,2.57 ; -11.43,1.27 -11.43,2.57 ; -13.97,1.27 -13.97,2.57 ; -16.51,1.27 -16.51,2.57 ; -19.05,1.27 -19.05,2.57 ; -21.59,1.27 -21.59,2.57 ; -24.13,1.27 -24.13,2.57
  silkscreen extent -25.37,-2.54 25.35,2.55, body extent -25.4,-3.6 25.4,3.6, height 3.6
"HDR2X20 SMD Female"#2 [mm] "Connector SMD Female reverse mount 20x2 Position"
  rrect20% 1.2x1.83 smd paste-5: 1(-24.13,-3.185) 2(-24.13,3.185) 3(-21.59,-3.185) 4(-21.59,3.185) 5(-19.05,-3.185) 6(-19.05,3.185) 7(-16.51,-3.185) 8(-16.51,3.185) 9(-13.97,-3.185) 10(-13.97,3.185) 11(-11.43,-3.185) 12(-11.43,3.185) 13(-8.89,-3.185) 14(-8.89,3.185) 15(-6.35,-3.185) 16(-6.35,3.185) 17(-3.81,-3.185) 18(-3.81,3.185) 19(-1.27,-3.185) 20(-1.27,3.185) 21(1.27,-3.185) 22(1.27,3.185) 23(3.81,-3.185) 24(3.81,3.185) 25(6.35,-3.185) 26(6.35,3.185) 27(8.89,-3.185) 28(8.89,3.185) 29(11.43,-3.185) 30(11.43,3.185) 31(13.97,-3.185) 32(13.97,3.185) 33(16.51,-3.185) 34(16.51,3.185) 35(19.05,-3.185) 36(19.05,3.185) 37(21.59,-3.185) 38(21.59,3.185) 39(24.13,-3.185) 40(24.13,3.185)
  rrect30% 1.8x1.8 hole 1.1: 1(-24.13,-1.27)
  round 1.8 hole 1.1: 2(-24.13,1.27) 3(-21.59,-1.27) 4(-21.59,1.27) 5(-19.05,-1.27) 6(-19.05,1.27) 7(-16.51,-1.27) 8(-16.51,1.27) 9(-13.97,-1.27) 10(-13.97,1.27) 11(-11.43,-1.27) 12(-11.43,1.27) 13(-8.89,-1.27) 14(-8.89,1.27) 15(-6.35,-1.27) 16(-6.35,1.27) 17(-3.81,-1.27) 18(-3.81,1.27) 19(-1.27,-1.27) 20(-1.27,1.27) 21(1.27,-1.27) 22(1.27,1.27) 23(3.81,-1.27) 24(3.81,1.27) 25(6.35,-1.27) 26(6.35,1.27) 27(8.89,-1.27) 28(8.89,1.27) 29(11.43,-1.27) 30(11.43,1.27) 31(13.97,-1.27) 32(13.97,1.27) 33(16.51,-1.27) 34(16.51,1.27) 35(19.05,-1.27) 36(19.05,1.27) 37(21.59,-1.27) 38(21.59,1.27) 39(24.13,-1.27) 40(24.13,1.27)
  Top Layer lines w1.2: 24.13,-2.57 24.13,-1.27 ; 21.59,-2.57 21.59,-1.27 ; 19.05,-2.57 19.05,-1.27 ; 16.51,-2.57 16.51,-1.27 ; 13.97,-2.57 13.97,-1.27 ; 11.43,-2.57 11.43,-1.27 ; 8.89,-2.57 8.89,-1.27 ; 6.35,-2.57 6.35,-1.27 ; 3.81,-2.57 3.81,-1.27 ; 1.27,-2.57 1.27,-1.27 ; -1.27,-2.57 -1.27,-1.27 ; -3.81,-2.57 -3.81,-1.27 ; -6.35,-2.57 -6.35,-1.61 -6.35,-1.27 ; -8.89,-2.57 -8.89,-1.27 ; -11.43,-2.57 -11.43,-1.27 ; -13.97,-2.57 -13.97,-1.27 ; -16.51,-2.57 -16.51,-1.27 ; -19.05,-2.57 -19.05,-1.27 ; -21.59,-2.57 -21.59,-1.27 ; -24.13,-2.57 -24.13,-1.27 ; 24.13,1.27 24.13,2.57 ; 21.59,1.27 21.59,2.57 ; 16.51,1.27 16.51,2.57 ; 13.97,1.27 13.97,2.57 ; 11.43,1.27 11.43,2.57 ; 8.89,1.27 8.89,2.57 ; 6.35,1.27 6.35,2.57 ; 3.81,1.27 3.81,2.57 ; 1.27,1.27 1.27,2.57 ; -1.27,1.27 -1.27,2.57 ; -3.81,1.27 -3.81,2.57 ; -6.35,1.27 -6.35,2.57 ; -8.89,1.27 -8.89,2.57 ; -11.43,1.27 -11.43,2.57 ; -13.97,1.27 -13.97,2.57 ; -16.51,1.27 -16.51,2.57 ; -19.05,1.27 -19.05,2.57 ; -21.59,1.27 -21.59,2.57 ; -24.13,1.27 -24.13,2.57
  silkscreen extent -25.37,-2.54 25.35,2.55, body extent -25.4,-3.6 25.4,3.6, height 3.6
"HDR2X20 SMD Female"#3 [mm] "Connector SMD Female reverse mount 20x2 Position"
  rrect20% 1.2x1.83 smd paste-5: 1(-24.13,-3.185) 2(-24.13,3.185) 3(-21.59,-3.185) 4(-21.59,3.185) 5(-19.05,-3.185) 6(-19.05,3.185) 7(-16.51,-3.185) 8(-16.51,3.185) 9(-13.97,-3.185) 10(-13.97,3.185) 11(-11.43,-3.185) 12(-11.43,3.185) 13(-8.89,-3.185) 14(-8.89,3.185) 15(-6.35,-3.185) 16(-6.35,3.185) 17(-3.81,-3.185) 18(-3.81,3.185) 19(-1.27,-3.185) 20(-1.27,3.185) 21(1.27,-3.185) 22(1.27,3.185) 23(3.81,-3.185) 24(3.81,3.185) 25(6.35,-3.185) 26(6.35,3.185) 27(8.89,-3.185) 28(8.89,3.185) 29(11.43,-3.185) 30(11.43,3.185) 31(13.97,-3.185) 32(13.97,3.185) 33(16.51,-3.185) 34(16.51,3.185) 35(19.05,-3.185) 36(19.05,3.185) 37(21.59,-3.185) 38(21.59,3.185) 39(24.13,-3.185) 40(24.13,3.185)
  rrect30% 1.8x1.8 hole 1.1: 1(-24.13,-1.27)
  round 1.8 hole 1.1: 2(-24.13,1.27) 3(-21.59,-1.27) 4(-21.59,1.27) 5(-19.05,-1.27) 6(-19.05,1.27) 7(-16.51,-1.27) 8(-16.51,1.27) 9(-13.97,-1.27) 10(-13.97,1.27) 11(-11.43,-1.27) 12(-11.43,1.27) 13(-8.89,-1.27) 14(-8.89,1.27) 15(-6.35,-1.27) 16(-6.35,1.27) 17(-3.81,-1.27) 18(-3.81,1.27) 19(-1.27,-1.27) 20(-1.27,1.27) 21(1.27,-1.27) 22(1.27,1.27) 23(3.81,-1.27) 24(3.81,1.27) 25(6.35,-1.27) 26(6.35,1.27) 27(8.89,-1.27) 28(8.89,1.27) 29(11.43,-1.27) 30(11.43,1.27) 31(13.97,-1.27) 32(13.97,1.27) 33(16.51,-1.27) 34(16.51,1.27) 35(19.05,-1.27) 36(19.05,1.27) 37(21.59,-1.27) 38(21.59,1.27) 39(24.13,-1.27) 40(24.13,1.27)
  Top Layer lines w1.2: 24.13,-2.57 24.13,-1.27 ; 21.59,-2.57 21.59,-1.27 ; 19.05,-2.57 19.05,-1.27 ; 16.51,-2.57 16.51,-1.27 ; 13.97,-2.57 13.97,-1.27 ; 11.43,-2.57 11.43,-1.27 ; 8.89,-2.57 8.89,-1.27 ; 6.35,-2.57 6.35,-1.27 ; 3.81,-2.57 3.81,-1.27 ; 1.27,-2.57 1.27,-1.27 ; -1.27,-2.57 -1.27,-1.27 ; -3.81,-2.57 -3.81,-1.27 ; -6.35,-2.57 -6.35,-1.27 ; -8.89,-2.57 -8.89,-1.27 ; -11.43,-2.57 -11.43,-1.27 ; -13.97,-2.57 -13.97,-1.27 ; -16.51,-2.57 -16.51,-1.27 ; -19.05,-2.57 -19.05,-1.27 ; -21.59,-2.57 -21.59,-1.27 ; -24.13,-2.57 -24.13,-1.27 ; 24.13,1.27 24.13,2.57 ; 21.59,1.27 21.59,2.57 ; 19.05,1.27 19.05,2.57 ; 16.51,1.27 16.51,2.57 ; 13.97,1.27 13.97,2.57 ; 11.43,1.27 11.43,2.57 ; 8.89,1.27 8.89,2.57 ; 6.35,1.27 6.35,2.57 ; 3.81,1.27 3.81,2.57 ; 1.27,1.27 1.27,2.57 ; -1.27,1.27 -1.27,2.57 ; -3.81,1.27 -3.81,2.57 ; -6.35,1.27 -6.35,2.57 ; -8.89,1.27 -8.89,2.57 ; -11.43,1.27 -11.43,2.57 ; -13.97,1.27 -13.97,2.57 ; -16.51,1.27 -16.51,2.167 -16.51,2.57 ; -19.05,1.27 -19.05,2.57 ; -21.59,1.27 -21.59,2.57 ; -24.13,1.27 -24.13,2.57
  silkscreen extent -25.37,-2.54 25.35,2.55, body extent -25.4,-3.6 25.4,3.6, height 3.6
"HDR 1x3" [mm]
  rrect50% 1.7x1.7 hole 1.1: 1(0,0)
  round 1.7 hole 1.1: 2(2.54,0) 3(5.08,0)
  silkscreen extent -1.27,-1.27 6.33,1.27, body extent -1.27,-1.27 6.35,1.27, height 8.65
"IC SOT23-5" [mm] "SOT23, 5-Leads, Body 3,0x3,4mm (max), Pitch 0,95mm, IPC Medium Density"
  rrect20% 1.2x0.7 smd paste-0.025 mask+0.05: 1(-1.173,0.95) 2(-1.173,0) 3(-1.173,-0.95) 4(1.173,-0.95) 5(1.173,0.95)
  silkscreen extent -1.42,-1.5 0.3,2.07, body extent -1.51,-1.5 1.51,1.5, height 1.11
"LC 0504 (1210 metric)" [mm]
  rrect15% 0.5x0.4 smd paste-0.015 mask+0.02: 1(-0.6,0.3) 2(0.6,0.3) 3(0.6,-0.3) 4(-0.6,-0.3)
  silkscreen extent 0,-0.25 0,0.25, body extent -0.65,-0.5 0.65,0.5, height 0.81
"LC 0603 (1608 metric)" [mm] "Generic chip Emi filter"
  rrect25% 0.6x0.9 smd paste-0.05: 1(0.8,0) 2(-0.8,0)
  rrect25% 0.45x1.5 smd paste-0.05: 3(0,0)
  body extent -0.8,-0.4 0.8,0.4, height 0.6
"LL 0603 (1608 metric)" [mm] "Generic chip capacitor"
  rrect25% 0.8x0.9 smd paste-0.05: 1(0.75,0) 2(-0.75,0)
  silkscreen extent 0,-0.4 0,0.4, body extent -0.8,-0.4 0.8,0.4, height 0.8
"LL 0805 (2012 metric)" [mm] "Generic chip capacitor"
  rrect25% 1.1x1.3 smd paste-0.05: 1(0.95,0) 2(-0.95,0)
  silkscreen extent 0,-0.6 0,0.6, body extent -1,-0.63 1,0.63, height 1.25
"microSDHinge JAE E" [mm]
  rrect20% 0.8x1.8 smd mask+0.07: 1(3.85,-6.225) 2(2.75,-6.225) 3(1.65,-6.225) 4(0.55,-6.225) 5(-0.55,-6.225) 6(-1.65,-6.225) 7(-2.75,-6.225) 8(-3.85,-6.225)
  rrect20% 1.8x1.4 smd: 9(-3.25,-8.225) 12(3.25,-8.225)
  rrect20% 1.8x1.2 smd: 10(-4.05,5.325) 11(3.3,5.325)
  body extent -7.2,-10 6.85,6.3, height 1.9
"PULSANTE SMD S" [mm]
  rrect15% 1.5x2 smd: 1(0.01,3.7) 2(0.01,-3.7)
  silkscreen extent -1.69,-5.2 1.81,5.2, body extent -1.75,-4.25 1.75,4.25, height 4.92
"QFN24 - 4x4mm" [mm] "LAN8720"
  rrect20% 0.8x0.3 smd paste-0.03 mask+0.025: 1(-1.95,1.25) 6(-1.95,-1.25) 13(1.95,-1.25) 18(1.95,1.25)
  rrect20% 0.9x0.3 smd paste-0.03 mask+0.025: 2(-1.95,0.75) 3(-1.95,0.25) 4(-1.95,-0.25) 5(-1.95,-0.75) 14(1.95,-0.75) 15(1.95,-0.25) 16(1.95,0.25) 17(1.95,0.75)
  rrect20% 0.3x0.8 smd paste-0.03 mask+0.025: 7(-1.25,-1.95) 12(1.25,-1.95) 19(1.25,1.95) 24(-1.25,1.95)
  rrect20% 0.3x0.9 smd paste-0.03 mask+0.025: 8(-0.75,-1.95) 9(-0.25,-1.95) 10(0.25,-1.95) 11(0.75,-1.95) 20(0.75,1.95) 21(0.25,1.95) 22(-0.25,1.95) 23(-0.75,1.95)
  round 0.8 smd mask+0.025: 25(-0.7,0.7) 25(-0.7,-0.7) 25(0.7,0.7) 25(0.7,-0.7)
  rrect5% 2.5x2.5 smd paste-5 mask+0.025: 25(0,0)
  round 0.7 smd mask+0.025: 25(0,0)
  silkscreen extent -2,-2 2.21,3.21, body extent -2.01,-2.01 2.01,2.01, height 0.82
RJLD-260TC1 [mm] "RJ45 Ethernet connector by TAIMAG"
  rrect50% 1.7x1.7 hole 1.05: 1(-4.445,3.3)
  round 1.7 hole 1.05: 2(-3.175,5.84) 3(-1.905,3.3) 4(-0.635,5.84) 5(0.635,3.3) 6(1.905,5.84) 7(3.175,3.3) 8(4.445,5.84)
  round 2 hole 1.05: 9(-6.35,-7.95) 10(-3.81,-6.43) 11(3.81,-7.95) 12(6.35,-6.43)
  round 3.4 hole 2: 13(-7.79,0) 14(7.79,0)
  round 2.95 hole 3.2 unplated: MH3(-5.715,-3.05) MH4(5.715,-3.05)
  silkscreen extent -7.89,-9.3 7.88,7.71, body extent -8.88,-14.28 9.02,6.72, height 14.57
"RR 0402S 1005m SOLDER" [mm] "Chip Resistor - Surface Mount 0402 (1005 metric)  with small footprint"
  rrect15% 0.5x0.56 smd paste-0.01 mask+0.04: 1(0.45,0) 2(-0.45,0)
  silkscreen extent 0,-0.26 0,0.26, body extent -0.5,-0.25 0.5,0.25, height 0.35
"RR 0603 (1608 metric)" [mm] "Chip Resistor - Surface Mount 0603 (1608 metric)"
  rrect20% 0.8x0.9 smd paste-0.05: 1(0.75,0) 2(-0.75,0)
  silkscreen extent 0,-0.4 0,0.4, body extent -0.8,-0.4 0.8,0.4, height 0.45
"RR 0805 (2012 metric)" [mm] "Chip Resistor - Surface Mount 0805 (2012 metric)"
  rrect15% 1.1x1.3 smd: 1(0.95,0) 2(-0.95,0)
  silkscreen extent 0,-0.6 0,0.6, body extent -1,-0.63 1,0.63, height 0.45
"RR 1206 (3216 metric)" [mm] "Chip Resistor - Surface Mount 1206 (3216 metric)"
  rrect15% 1.1x1.7 smd: 1(1.5,0) 2(-1.5,0)
  silkscreen extent -0.6,-0.8 0.6,0.8, body extent -1.6,-0.8 1.6,0.8, height 0.55
"SOT23 for IRLML6402" [mm] "SOT-23; 3 Leads; Body 3.1 x 2.5 mm, inc. leads (LxW max), Alternate Lead Configuration"
  rrect25% 0.9x1.1 smd paste-0.05: 1(-0.95,-1.05) 2(0.95,-1.05) 3(0,1.02)
  silkscreen extent -1.3,-1.61 1.3,1.35, body extent -1.5,-1.33 1.5,1.33, height 1.1
"SOT23 generic" [mm] "SOT-23; 3 Leads; Body 3.1 x 2.5 mm, inc. leads (LxW max), Alternate Lead Configuration"
  rrect25% 0.9x1.1 smd paste-0.05: 1(-0.95,-1.05) 2(0.95,-1.05) 3(0,1.02)
  silkscreen extent -1.3,0.87 1.3,1.35, body extent -1.5,-1.33 1.5,1.33, height 1.1
"Supercap AVX 8x16x18" [mm] "AVX serie SCMR"
  rrect50% 2.5x2.5 hole 1: 1(-5.75,0) 2(5.75,0)
  silkscreen extent -8.01,-4.01 8.02,4.01, body extent -8.03,-4.01 7.95,3.99, height 18
"TP 1.3mm" [mm] "Test Point"
  round 1.3 smd paste-3 mask-0.15: 1(0,0)
"USB2.0-4H4 3D FOX" [mm] "Connector; USB1.1, Type A, Thru-Hole; 4 Position; Right Angle"
  rrect50% 1.6x1.9 hole 1.1: 1(-6,0)
  oval 1.6x1.9 hole 1.1: 2(-4,0) 3(-2,0) 4(0,0)
  round 2.5 hole 1.7: 5(-6.73,2.72) 6(-6.73,-2.72) 7(0.27,-2.72) 8(0.27,2.72)
  silkscreen extent -7.34,-2.9 -1.26,2.86, body extent -18.52,-3.6 1.14,3.52, height 14.55
"USB Micro B - Extended" [mm]
  rrect20% 0.4x1.8 smd mask+0.05: 1(-1.3,2.95) 2(-0.65,2.95) 3(0,2.95) 4(0.65,2.95) 5(1.3,2.95)
  rrect15% 2.1x1.8 smd mask+0.05: 6(-2.425,2.95) 11(2.425,2.95)
  rrect15% 1.7x2 smd mask+0.05: 7(-3.075,0.5) 10(3.075,0.5)
  rrect15% 1.425x1.5 smd mask+0.05: 8(-1,0.5) 9(1,0.5)
  silkscreen extent -3.8,1.6 3.8,4.1, body extent -4,-2.5 4,3.1, height 2.79
"XT DFN-LCC 3.2x2.5" [mm] "25 MHz"
  rrect15% 1.4x1.15 smd paste-0.025: 1(-1.1,-0.8) 2(1.1,-0.8) 3(1.1,0.8) 4(-1.1,0.8)
  silkscreen extent -2.1,-1.65 2.1,1.65, body extent -1.6,-1.25 1.6,1.25, height 0.55

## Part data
"25 MHz": "Test Point 1.3 mm"
"AB RoadRunner": library part "AB RoadRunner"
C1 C2 C3 C4 C6 C8 C9 C10 C11 C12 C25: library part "CC Ceramic Capacitor", "Capacitor, Multi Layer Ceramic"
C5 C13 C14 C15 C16 C17 C18 C19 C20 C21 C22 C23 C24 C26 C27: library part "CC Ceramic", "Capacitor, Multi Layer Ceramic"
C7: library part "CE Supercap", "Electrolytic Capacittor"
D1 D2: library part "DS Schottky Diode", "Schottky Diode"
DL1 DL2: library part "DL LED", "LED Light-emitting diode"
F1: library part "FUSE SMD", "Bourns Fuse"
J1: library part "JJ HDR 1x3 2.54mm"
J3 J4 J5 J6: "Header 20X2 SMD Female reverse mount"
J7: "USB 2.0 type A"
J8: "USB Micro B Digikey: 609-4050-2-ND"
J9 J13: "Header, 2-Pin Dual Mount Female 2mm"
J10: "Header, 6-Pin Male 6mm"
J11: "ETH connector RJLD-260TC1 TAIMAG"
L1 L2 L3 L4 L5 L6: library part "LF Ferrite", "Ferrite"
L7: library part "LL Inductor", "Power inductor 2uH2 0805"
L8: library part "LF Ferrite", "Ferrite 220 Ohm 2A 0805"
L9: library part "LF Ferrite", "Ferrite 120 Ohm 0603"
LC1 LC2 LC3: library part "LC Choke", "Common Mode Choke Coil Film Type"
LC4: library part "LC EMI Filter", "Ferrite 220 Ohm 2A 0805"
P1 P2: "SWITCH TACT 6MM 160GF H=4.3MM"
Q1: "3A P-Channel Logic MOSFET SOT23"
Q2 Q3: "100mA N-Channel Logic MOSFET SOT23"
R1 R2 R3 R4 R5 R6 R7 R8 R9 R10 R11 R12 R13 R14 R15 R16 R17 R18 R19 R20 R21 R22 R23 R24 R25 R26 R27 R28 R29 R30 R31 R32 R33 R34: library part "RR Resistor", "Resistor"
U1: library part "IC CM1624"
U2: library part "IC LAN8720"
U3: library part AP7333, "LDO Regulator SOT-23"
U6: "1.7MHz, 1A, High Efficiency, Low Ripple, Adjustable Output Voltage Step-down Converter"
uSD: library part microSDHinge
Y1: library part "XT QUAD"

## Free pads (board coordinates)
  rrect15% 5x5 hole 3.2 mask+0.4: 8(-45.892,-45.492) 8(-45.892,45.508) 8(45.608,-45.492) 8(45.608,45.508)
  round 1 smd paste-3 mask-0.03: 9(-39.82,17.78) 9(-36.2,16.67) 9(-7.57,-33.51) 9(-6.766,-32.186) 9(-5.46,-33.56) 9(-3.48,-33.96) 9(-1.166,-33.386) 9(-0.8,-31.8)
  round 0 hole 1 unplated paste-3 mask+0.55: 10(-50.193,-49.99) 11(-50.19,50.008) 12(50.307,50) 13(50.31,-49.99)

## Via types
v1: diameter 0.5, hole 0.25, Top Layer to Bottom Layer, tented both sides, 469 vias
v2: diameter 0.6, hole 0.3, Top Layer to Bottom Layer, tented both sides, 200 vias
v3: diameter 1.27, hole 0.7, Top Layer to Bottom Layer, tented both sides, 72 vias
v4: diameter 0.7, hole 0.3, Top Layer to Bottom Layer, tented both sides, 20 vias
v5: diameter 0.9, hole 0.5, Top Layer to Bottom Layer, tented both sides, 19 vias
v6: diameter 0.7, hole 0.3, Top Layer to Bottom Layer, 8 vias
v7: diameter 1, hole 0.5, Top Layer to Bottom Layer, tented both sides, 6 vias
v8: diameter 1.7, hole 1.05, Top Layer to Bottom Layer, tented both sides, 5 vias
v9: diameter 3, hole 1.5, Top Layer to Bottom Layer, 3 vias
v10: diameter 1.7, hole 1.05, Top Layer to Bottom Layer, 3 vias
v11: diameter 0.56, hole 0.3, Top Layer to Bottom Layer, tented both sides, 1 vias
v12: diameter 0.8, hole 0.4, Top Layer to Bottom Layer, tented both sides, 1 vias

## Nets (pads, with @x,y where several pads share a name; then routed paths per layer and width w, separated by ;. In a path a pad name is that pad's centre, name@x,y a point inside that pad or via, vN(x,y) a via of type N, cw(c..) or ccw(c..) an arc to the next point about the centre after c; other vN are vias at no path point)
3V3: C3.1 C4.1 C5.2 D2.A J6.2 J6.4 J13.2 L7.2 R2.1 R3.2 R6.1 R7.1 R9.1 | length 96.2
  Top Layer w0.4: D2.A@-30.71,17.778 -29.424,17.778
  Top Layer w0.5: R9.1@44.32,21.92 R9.1@44.73,21.51 v10@44.73,20.16
  Top Layer w0.65: -0.97,14.77 R7.1@-0.01,14.77
  Top Layer w0.8: v3(-9.244,17.909) v3@-7.352,17.909 ; v3(-7.352,17.896) -6.529,17.896 v3(-5.489,18.936)
  Bottom Layer w0.5: -29.424,17.77 -29.411,17.77 -28.458,17.77 -25.924,20.304 -19.088,20.304 -18.672,20.72 -9.36,20.72 -7.352,18.712 v3(-7.352,17.896)
  Bottom Layer w0.8: v3(-9.244,17.909) -7.365,17.909 v3(-7.352,17.896) -6.529,17.896 v3(-5.489,18.936)
  Bottom Layer w1: v10(-1.98,16.41) 0.65,16.41 1.845,17.605 3.6,19.36 7.188,19.36 10.248,16.3 17.58,16.3 18.245,15.635 43.694,15.635 ; 44.17,15.635 44.17,19.17 v10(44.76,19.76)
  Bottom Layer w1.2: J6.4@43.2,10.16 44.17,11.13 44.17,12.7 44.17,15.635
  other v4: -29.424,17.388 -29.411,18.182
3V3_ETH: C16.2 C24.1 Q1.2 R9.2 R10.1 R11.1 R12.2 R13.1 | length 49
  Top Layer w0.3: v5@12.43,20.27 12.44,20.26 R13.1@12.44,19.47 ; R11.1@33.65,20.44 33.65,21.14 33.68,21.17 ; 34.93,21.17 34.94,21.16 C16.2@34.94,20.43
  Top Layer w0.4: R10.1@31.84,22.99 32.749,22.99 ; C24.1@36.28,21.17 C24.1@36.33,21.12
  Top Layer w0.5: v3(31.678,24.462) 32.034,24.462 32.805,23.691 32.805,22.934 ; Q1.2@32.03,21.17 Q1.2@32.425,21.17 ; Q1.2@32.506,21.251 Q1.2@32.425,21.17 ; 32.749,22.99 32.805,22.934 ; 44.72,24.46 44.71,24.45 38.2,24.45 38.01,24.26 38.01,22.35 36.83,21.17 36.28,21.17 34.93,21.17 33.68,21.17 32.805,21.17 ; R12.2@44.72,25.49 44.73,25.48 R9.2@44.73,23.41 ; Q1.2@32.425,21.17 32.805,21.17 ; 32.805,21.17 32.805,22.934
  Signal Layer 2 w0.5: v5(12.37,20.52) 12.62,20.27 13.35,20.27 14.62,19 22.11,19 23.03,19.92 30.07,19.92 31.678,21.528 v3@31.678,24.458 ; v3@31.42,24.2 v3@31.678,24.458 ; v3(31.678,24.462) v3@31.678,24.458
3V3_IN: "AB RoadRunner.J2-1" "AB RoadRunner.J2-2" "AB RoadRunner.J2-3" "AB RoadRunner.J2-4" "AB RoadRunner.J2-5" "AB RoadRunner.J2-6" "AB RoadRunner.J2-7" "AB RoadRunner.J2-8" C11.1 J13.1 R7.2 | length 59.1
  Top Layer w0.2: 9.2,-1.4 9.207,-1.392 10.539,-1.392 ; v8(9.89,2.01) v8@10.145,1.755 ; 13.705,-1.392 14.917,-1.392
  Top Layer w0.22: 9.34,-0.99 9.342,-0.992 10.595,-0.992 ; 9.6,-0.59 9.603,-0.593 10.595,-0.593 ; 13.705,-0.992 14.75,-0.992 ; 13.705,-0.593 13.877,-0.593
  Top Layer w0.3: 9.34,-0.99 8.91,-0.56 8.91,1.61 9.31,2.01 v8(9.89,2.01) 9.41,1.53 9.41,-0.4 9.6,-0.59 ; v8@10.145,1.755 10.145,0.1 10.395,-0.15 ; 13.69,-0.15 13.69,1.41 v8@14.52,2.24 ; 13.877,-0.593 14.327,-0.593 v8@14.9,-0.02 ; 14.75,-0.94 15.12,-0.57 v8@15.12,-0.08
  Top Layer w0.4: 9.2,-1.4 9,-1.4 8.42,-0.82 8.42,2.01 8.63,2.22 9.68,2.22 v8(9.89,2.01) ; 14.917,-1.392 15.078,-1.392 15.82,-0.65 15.82,-0.32 v8(15.12,0.38)
  Top Layer w0.65: R7.2@3.02,14.67 4.063,14.67
  Top Layer w0.7: 4.063,14.67 4.65,15.257
  Top Layer w0.8: C11.1@2.72,11.89 4.23,11.89
  Top Layer w1: 4.23,11.89 4.65,12.31 ; v8(4.47,10.37) 4.65,10.55 4.65,15.53 ; 4.65,15.257 4.65,15.53 ; J13.1@4.65,17.34 4.65,15.53
  Bottom Layer w1: v8(4.6,13.19) 5.14,12.65 5.14,6.3 8.55,2.89 12.982,2.89 14.076,1.796 14.67,1.202 v8@14.67,0.38
  other v8: 14.58,2.3
3V3_IO_ETH: L8.1 Q1.3 R10.2 R14.1 R19.1 U2.9 | length 37.8
  Top Layer w0.2: v2@13.92,24.9 14.47,25.45 U2.9@16.35,25.45
  Top Layer w0.3: R14.1@13.77,21.08 13.77,21.36 v2(14.15,21.74) ; R19.1@22.2,20.68 23.72,20.68
  Top Layer w0.4: 29.659,22.99 R10.2@30.34,22.99
  Top Layer w0.5: v2(13.38,24.21) 13.92,24.75 v2@13.92,24.9 ; 23.72,20.68 24.82,21.78 27.61,21.78 29.07,21.78 v3(29.13,21.72) ; L8.1@28.2,20.21 28.29,20.21 29.13,21.05 ; 29.659,22.99 29.13,22.461 v3(29.13,21.72) ; Q1.3@29.96,20.22 29.13,21.05 ; 29.13,21.05 v3(29.13,21.72)
  Signal Layer 2 w0.5: v2(13.88,24.92) 13.88,24.71 v2(13.38,24.21) 13.42,24.17 13.42,23.45 14.15,22.72 v2(14.15,21.74) 14.66,21.23 16.692,21.23 17.22,21.758 17.22,21.832 17.648,22.26 18.252,22.26 20.122,20.39 21.38,20.39 22.58,21.59 29,21.59 v3(29.13,21.72)
3V3_IO_ETH_F: C1.1 C12.1 C15.2 C17.1 C18.1 J11.4 J11.5 L8.2 R15.2 R16.2 R17.2 R18.2 U2.1 U2.19 | length 65.7
  Top Layer w0.3: U2.1@19.55,27.15 19.55,27.215 19.835,27.5 v3(20.8,27.5) ; v3(20.89,23.01) 21.56,22.34 C15.2@22.4,22.34 ; 21.47,27.67 C18.1@22.22,27.67 ; v5(26.88,30.3) 26.9,30.28 R15.2@26.9,29.55 ; R16.2@28.89,29.55 28.89,29.92 v5(29.36,30.39) ; v5(30.72,30.31) 30.73,30.3 R17.2@30.73,29.55 ; R18.2@33.45,28.4 v3@35.16,28.4 ; 35.3,29.76 35.44,29.62 C1.1@36.28,29.62
  Top Layer w0.35: v3(24.23,18.62) v3@24.45,18.62 ; C12.1@34.82,25.59 34.82,26.71 v3(35.3,27.19)
  Top Layer w0.5: 20.5,23.78 20.89,23.39 v3(20.89,23.01) ; 24.23,17.74 24.25,17.72 C17.1@25.69,17.72 C17.1@25.89,17.72 ; v3@24.45,18.62 26.04,20.21 L8.2@26.7,20.21
  Top Layer w0.8: v3(24.23,17.088) v3(24.23,18.62)
  Top Layer w1: 34.71,30.35 35.3,29.76 v3(35.3,27.19)
  Bottom Layer w0.5: v3@20.8,23.1 v3(20.8,27.5) ; v3(20.89,23.01) 24.25,19.65 v3@24.25,18.62 ; v3@24.23,16.97 v3(24.23,18.62)
  Bottom Layer w0.6: v5(26.88,30.3) 27.36,30.78 29.36,30.78 30.72,30.78 31.55,30.78 32.31,30.02 v3(34.13,30.02) ; J11.5@31.115,35.99 31.115,34.72 J11.4@32.385,33.45 33.493,32.342 33.493,31.637 34.62,30.51 34.75,30.38
  Bottom Layer w0.8: v3(24.23,18.62) 24.25,18.62 26.73,18.62 27.85,19.74 29.86,19.74 35.38,25.26 v3@35.38,28.6
  other v3: 35.36,28.6 35.33,30.7
3V3_OUT: "AB RoadRunner.J1-18" "AB RoadRunner.J2-96" "AB RoadRunner.J2-98" "AB RoadRunner.J2-100" C10.1 C13.1 C14.1 C26.2 J6.34 J6.36 L2.1 R8.1 R12.1 R25.2 R26.2 U1.12 U3.1 uSD.4 | length 337.1
  Top Layer w0.2: -10.595,-3.393 v12@-9.742,-3.393 ; -3.85,-32.85 U1.12@-3.85,-31.97 ; 13.705,-18.998 14.226,-18.998 14.318,-19.09
  Top Layer w0.22: 13.705,-20.183 13.705,-19.793 ; 13.705,-19.392 14.079,-19.392
  Top Layer w0.25: -4.485,-34.685 -4.485,-33.485 -3.85,-32.85 ; 13.705,-20.183 14.32,-20.798 14.32,-22.49 15.79,-23.96 C10.1@16.75,-23.96 ; 14.079,-19.392 14.77,-20.083 14.77,-22.14 16.082,-23.452 16.445,-23.452 C10.1@16.606,-23.613 ; 14.319,-19.089 15.23,-20 15.23,-21.95 C10.1@16.65,-23.37
  Top Layer w0.3: -12.06,-41.55 C14.1@-12.06,-40.86 ; R8.1@27.05,-42.89 27.05,-41.81 ; 32.54,-41.7 32.57,-41.67 ; 34.64,-41.6 34.74,-41.7 ; 36.72,-41.7 R26.2@36.72,-40.31 ; R25.2@39.32,-40.33 39.32,-41.56 39.46,-41.7
  Top Layer w0.4: -6.39,-41.74 uSD.4@-5.08,-41.74 ; U3.1@32.25,-39.45 C26.2@33.72,-39.45 ; 33.75,-41.54 C26.2@33.75,-39.42
  Top Layer w0.5: C13.1@-14.12,-41.57 C13.1@-14.1,-41.55 -12.06,-41.55 -7.18,-41.55 -6.99,-41.74 -6.39,-41.74 ; -10.88,-41.5 -10.88,-36.41 -9.67,-35.2 -5,-35.2 -4.485,-34.685 ; 33.75,-41.54 33.91,-41.7 ; J6.36@42.555,-30.48 J6.36@43.18,-30.48 J6.36@45.095,-30.48 47.48,-30.48 ; J6.34@44.48,-27.94 J6.34@45.095,-27.94 47.48,-27.94 ; R12.1@44.72,27.39 44.72,28.67
  Top Layer w0.6: L2.1@-41.56,30.58 -41.56,29.61 -41.55,29.6 ; v3(-15.74,-41.05) -15.24,-41.55 C13.1@-14.1,-41.55 ; 17.13,-25.38 C10.1@17.13,-23.83
  Top Layer w0.7: v5(-42.23,29.6) -41.45,29.6 ; -41.55,29.6 v5(-40.77,29.6)
  Top Layer w1: v9(-17.4,-39) -16.13,-40.27 v3@-16.13,-41.44 ; v3(-16.13,-42.32) -14.88,-43.57 -14.1,-43.57 -12.33,-45.34 -9.94,-45.34 -8.17,-47.11 6.84,-47.11 8.45,-45.5 10.13,-45.5 17.13,-38.5 ; 17.13,-25.38 17.13,-38.5 ; 44.74,29.03 46.199,29.03 47.48,27.749 47.48,-27.94 47.48,-30.48 47.48,-36.05 41.83,-41.7 39.46,-41.7 36.72,-41.7 34.74,-41.7 33.91,-41.7 32.54,-41.7 25.991,-41.7 24.598,-40.307 18.937,-40.307 17.13,-38.5
  Top Layer w1.5: v3(-16.13,-42.32) -16.13,-41.44 v3(-15.74,-41.05)
  Signal Layer 2 w1: v9(-17.4,-39) -16.13,-40.27 v3(-16.13,-42.32)
  Bottom Layer w0.5: v5(-42.23,29.6) -43.71,28.12 -43.71,26.49 -41.21,23.99 -37.27,23.99 -35.62,22.34 -35.62,20.24 -31.68,16.3 -28.63,16.3 -28.03,16.9 -24.56,16.9 -20.65,12.99 -18.46,12.99 -17.26,11.79 -15.05,11.79 -14.21,10.95 -10.86,10.95 -8.39,8.48 -8.39,-3.29 ; v9@-16.68,-37.82 -14.21,-35.35 -12.75,-35.35 -8.99,-31.59 -8.99,-30.97 -8.11,-30.09 -8.11,-26.46 -5.59,-23.94 -5.59,-13.6 -7,-12.19 -7,-4.63 -8.31,-3.32 v12(-9.66,-3.32)
  Bottom Layer w0.7: v5(-42.23,29.6) v5(-40.77,29.6)
  Bottom Layer w1: v9(-17.4,-39) -16.13,-40.27 -16.13,-41.44 -16.13,-41.49 v3(-16.13,-42.32)
  Bottom Layer w1.5: v3(-16.13,-42.32) -16.13,-41.49 -16.13,-41.44 v3(-15.74,-41.05)
5V0: C2.1 L3.1 R1.1 R4.1 R28.1 U6.4 | length 48.7
  Top Layer w0.3: R28.1@-42.704,27.953 -42.702,27.955 -41.189,27.955 R1.1@-39.591,27.955 ; U6.4@-10.53,16.46 -9.643,16.46 -9.177,15.994 -9.177,15.65 R4.1@-9.177,15.597
  Top Layer w0.4: -11.27,21.6 -11.27,22.01 L3.1@-11.27,23.103
  Top Layer w0.6: -10.766,17.475 -10.53,17.239 U6.4@-10.53,16.46
  Top Layer w0.7: C2.1@-12.958,20.628 -11.319,20.628 -11.257,21.488
  Top Layer w1: -11.257,21.89 -11.257,21.488 -11.291,19.023 -10.766,18.498 -10.766,17.475
  Bottom Layer w0.4: v4(-41.189,27.673) -34.733,27.673 -32.54,25.48 -27.77,25.48 -26.86,26.39 -19.69,26.39 -17.29,23.99 -12.31,23.99 -10.54,22.22 v3(-10.54,22.01)
BOOT_OFF: "AB RoadRunner.J1-98" J3.37 R34.2 | length 64.7
  Top Layer w0.2: J3.37@-45.095,-33.02 -46.53,-33.02 -46.87,-33.36 -46.87,-37.07 -43.36,-40.58 R34.2@-36.73,-40.58 ; v1@-11.447,-19.392 -10.595,-19.392
  Signal Layer 2 w0.2: -41.905,-34.3 -37.354,-34.3 -33.734,-37.92 -22.38,-37.92 -18.57,-34.11 -18.57,-26.55 -15.45,-23.43 -14.2,-23.43 -11.701,-20.931 -11.701,-20.105 -11.45,-19.854 v1(-11.45,-19.39)
  Signal Layer 2 w0.35: J3.37@-43.188,-33.028 -41.917,-34.3
BU_RXD: "AB RoadRunner.J1-26" J3.6 | length 43.3
  Top Layer w0.2: -10.595,-4.992 -9.997,-4.992 -9.67,-5.32 v1(-9.56,-5.32)
  Bottom Layer w0.2: -38.912,7.581 -35.399,7.581 -31.55,11.43 -24.78,11.43 -20.57,7.22 -20.57,2.86 -13,-4.71 -11.06,-4.71 -10.45,-5.32 v1(-9.56,-5.32)
  Bottom Layer w0.35: J3.6@-40.64,7.581 -38.912,7.581
COMPN: "AB RoadRunner.J1-12" J3.5 | length 39.2
  Top Layer w0.2: v1@-11.4,-2.193 -10.595,-2.193
  Signal Layer 2 w0.2: -41.992,6.34 -35.19,6.34 -32.64,8.89 -22.796,8.89 -21.122,7.216 -21.122,6.541 -12.401,-2.18 v1(-11.4,-2.18)
  Signal Layer 2 w0.35: J3.5@-43.226,7.574 -41.992,6.34
COMPP: "AB RoadRunner.J1-10" J3.3 | length 41.6
  Top Layer w0.2: -10.595,-1.793 v1@-9.742,-1.793
  Signal Layer 2 w0.2: -41.791,8.88 -36.85,8.88 -34.3,11.43 -24.615,11.43 -20.637,7.452 -20.637,6.871 -12.208,-1.558 -10.327,-1.558 -10.175,-1.71 v1(-9.74,-1.71)
  Signal Layer 2 w0.35: J3.3@-43.126,10.214 -41.791,8.88
EARTH1: C9.2 J11.8 J11.13 J11.14 pad.8@45.608,45.508 | length 28.9
  Top Layer w1: J11.14@23.96,39.29 J11.13@39.54,39.29 39.87,39.29 41.58,41
  Bottom Layer w1: J11.14@23.96,39.29 23.96,36.795 J11.8@27.305,33.45 ; J11.13@39.54,39.29 40.47,39.29 42.19,41.01
  other v7: 40.89,45.41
